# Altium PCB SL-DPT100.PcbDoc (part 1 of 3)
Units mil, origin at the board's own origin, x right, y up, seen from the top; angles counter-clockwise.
Board outline 2881.89 x 2169.29 mil, 4 copper layers (Top Layer, VCC, GND, Bottom Layer); 176 components, 168 nets, 589 pads, 369 vias.
Unrouted connection lines stored in the file: 2.
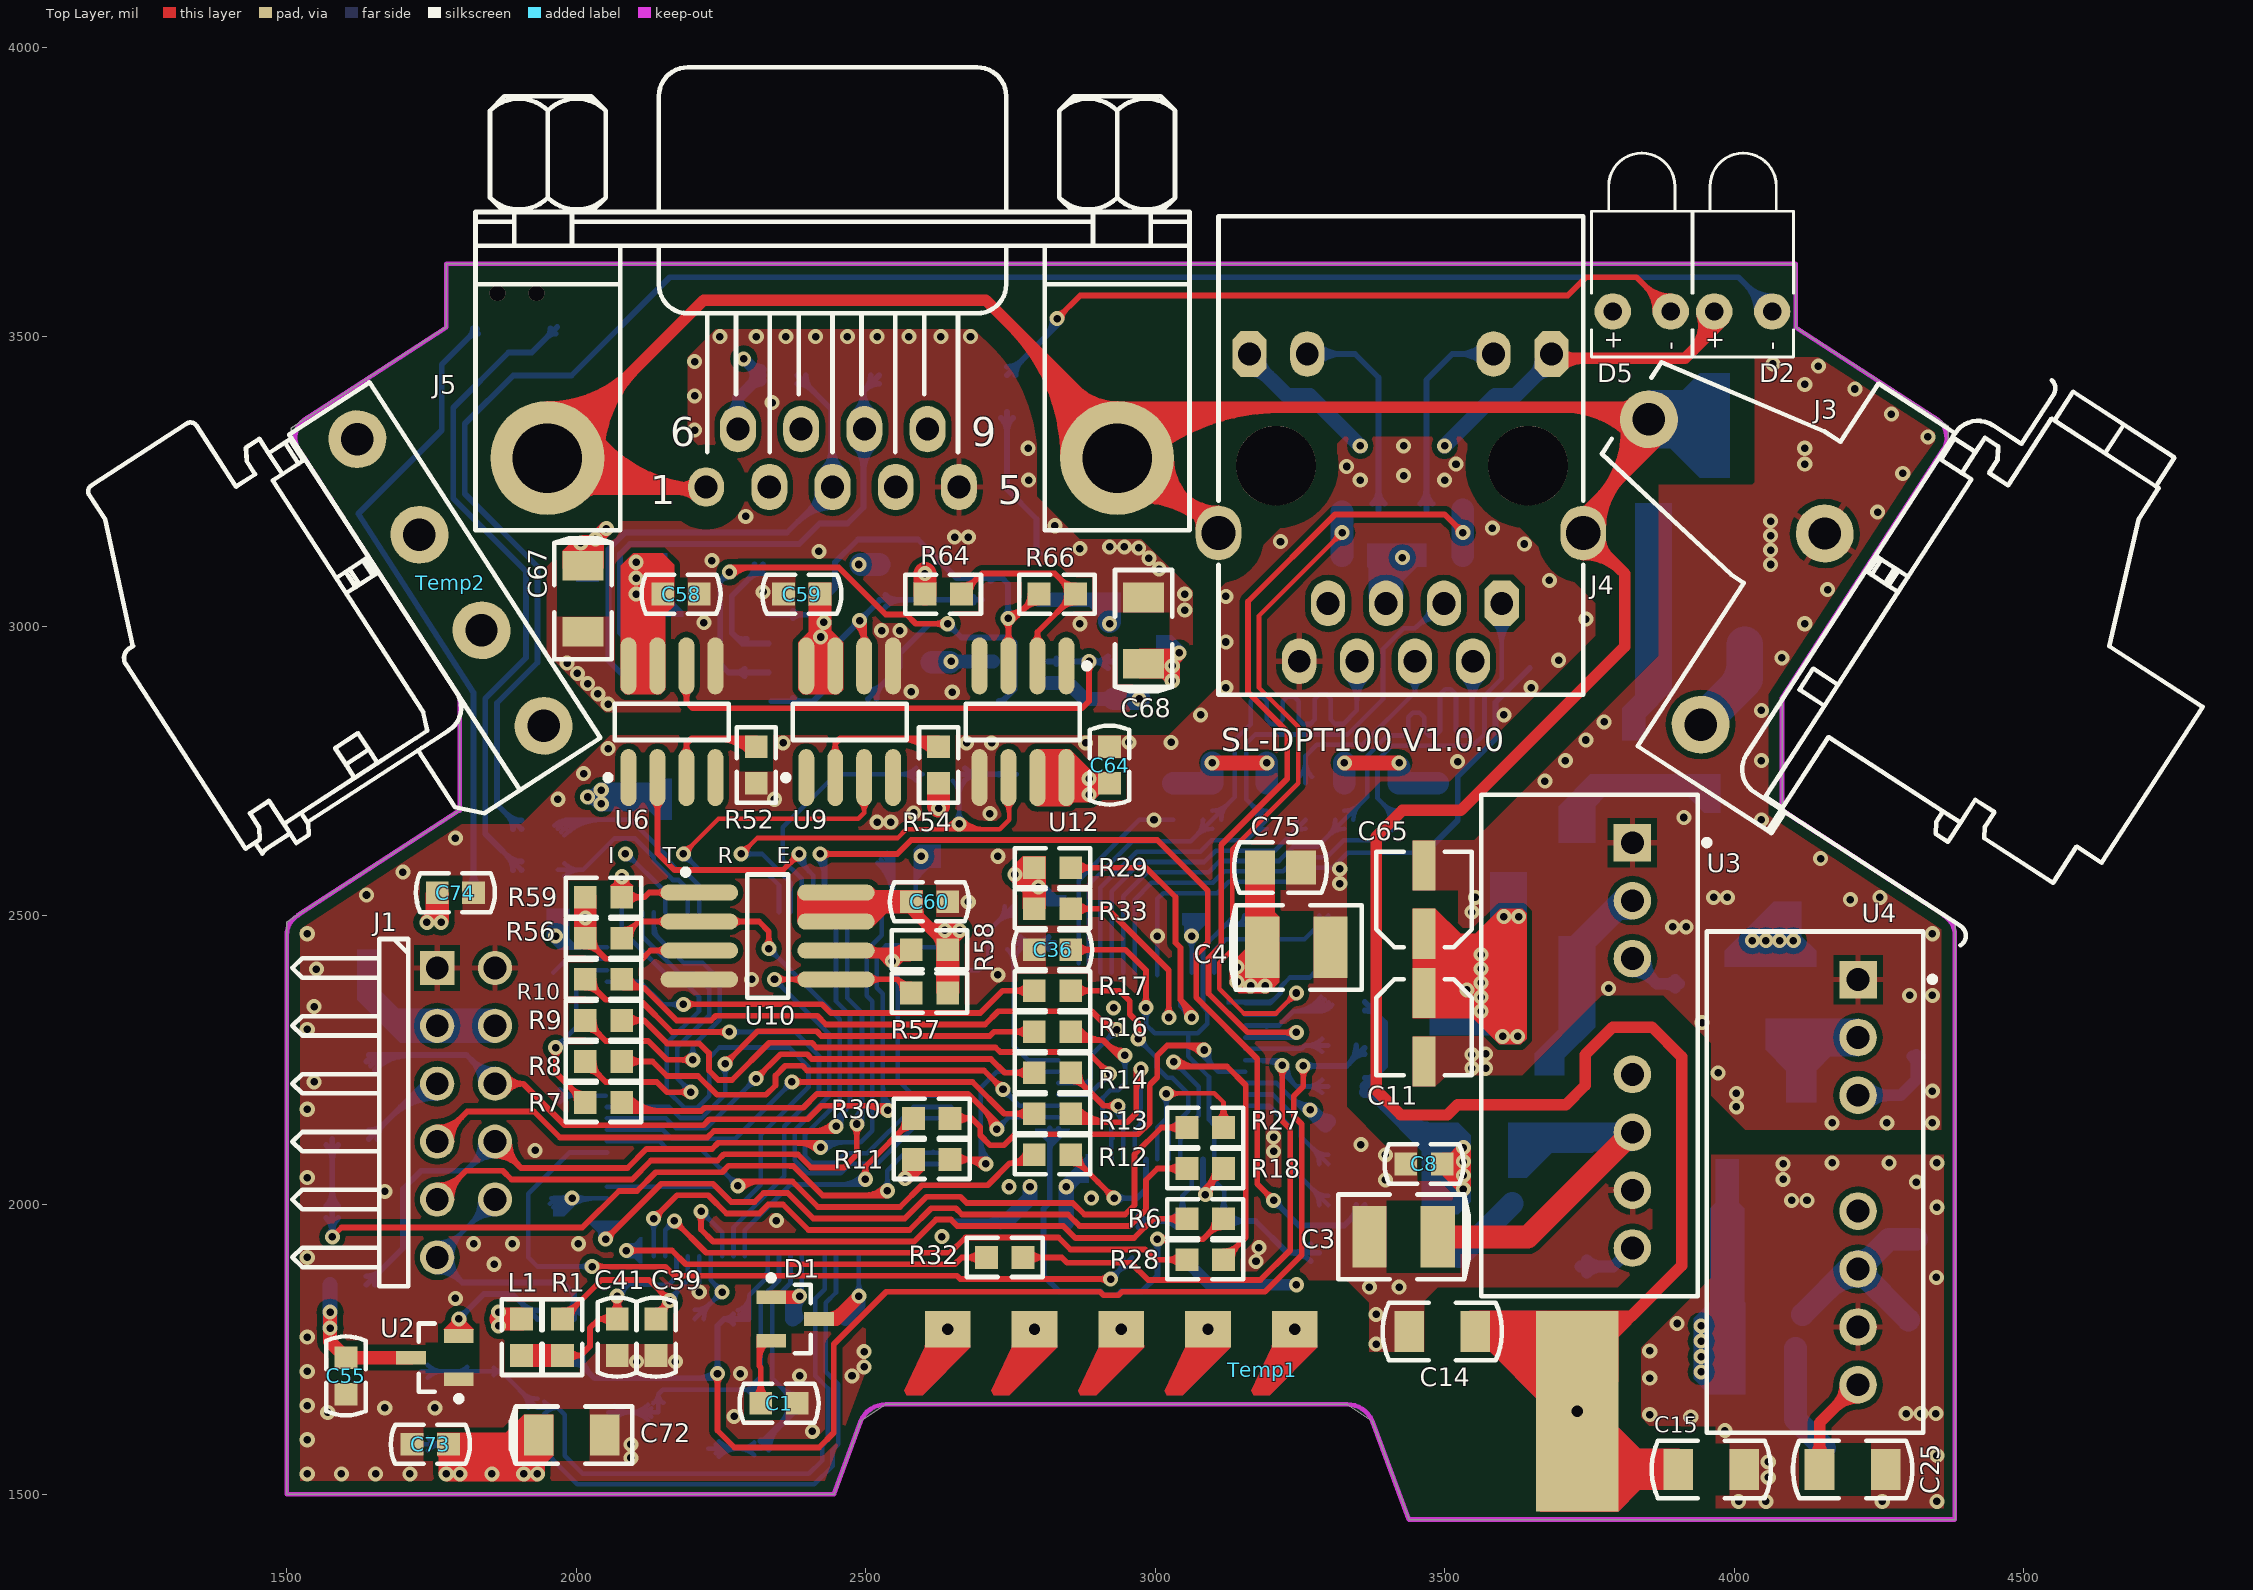
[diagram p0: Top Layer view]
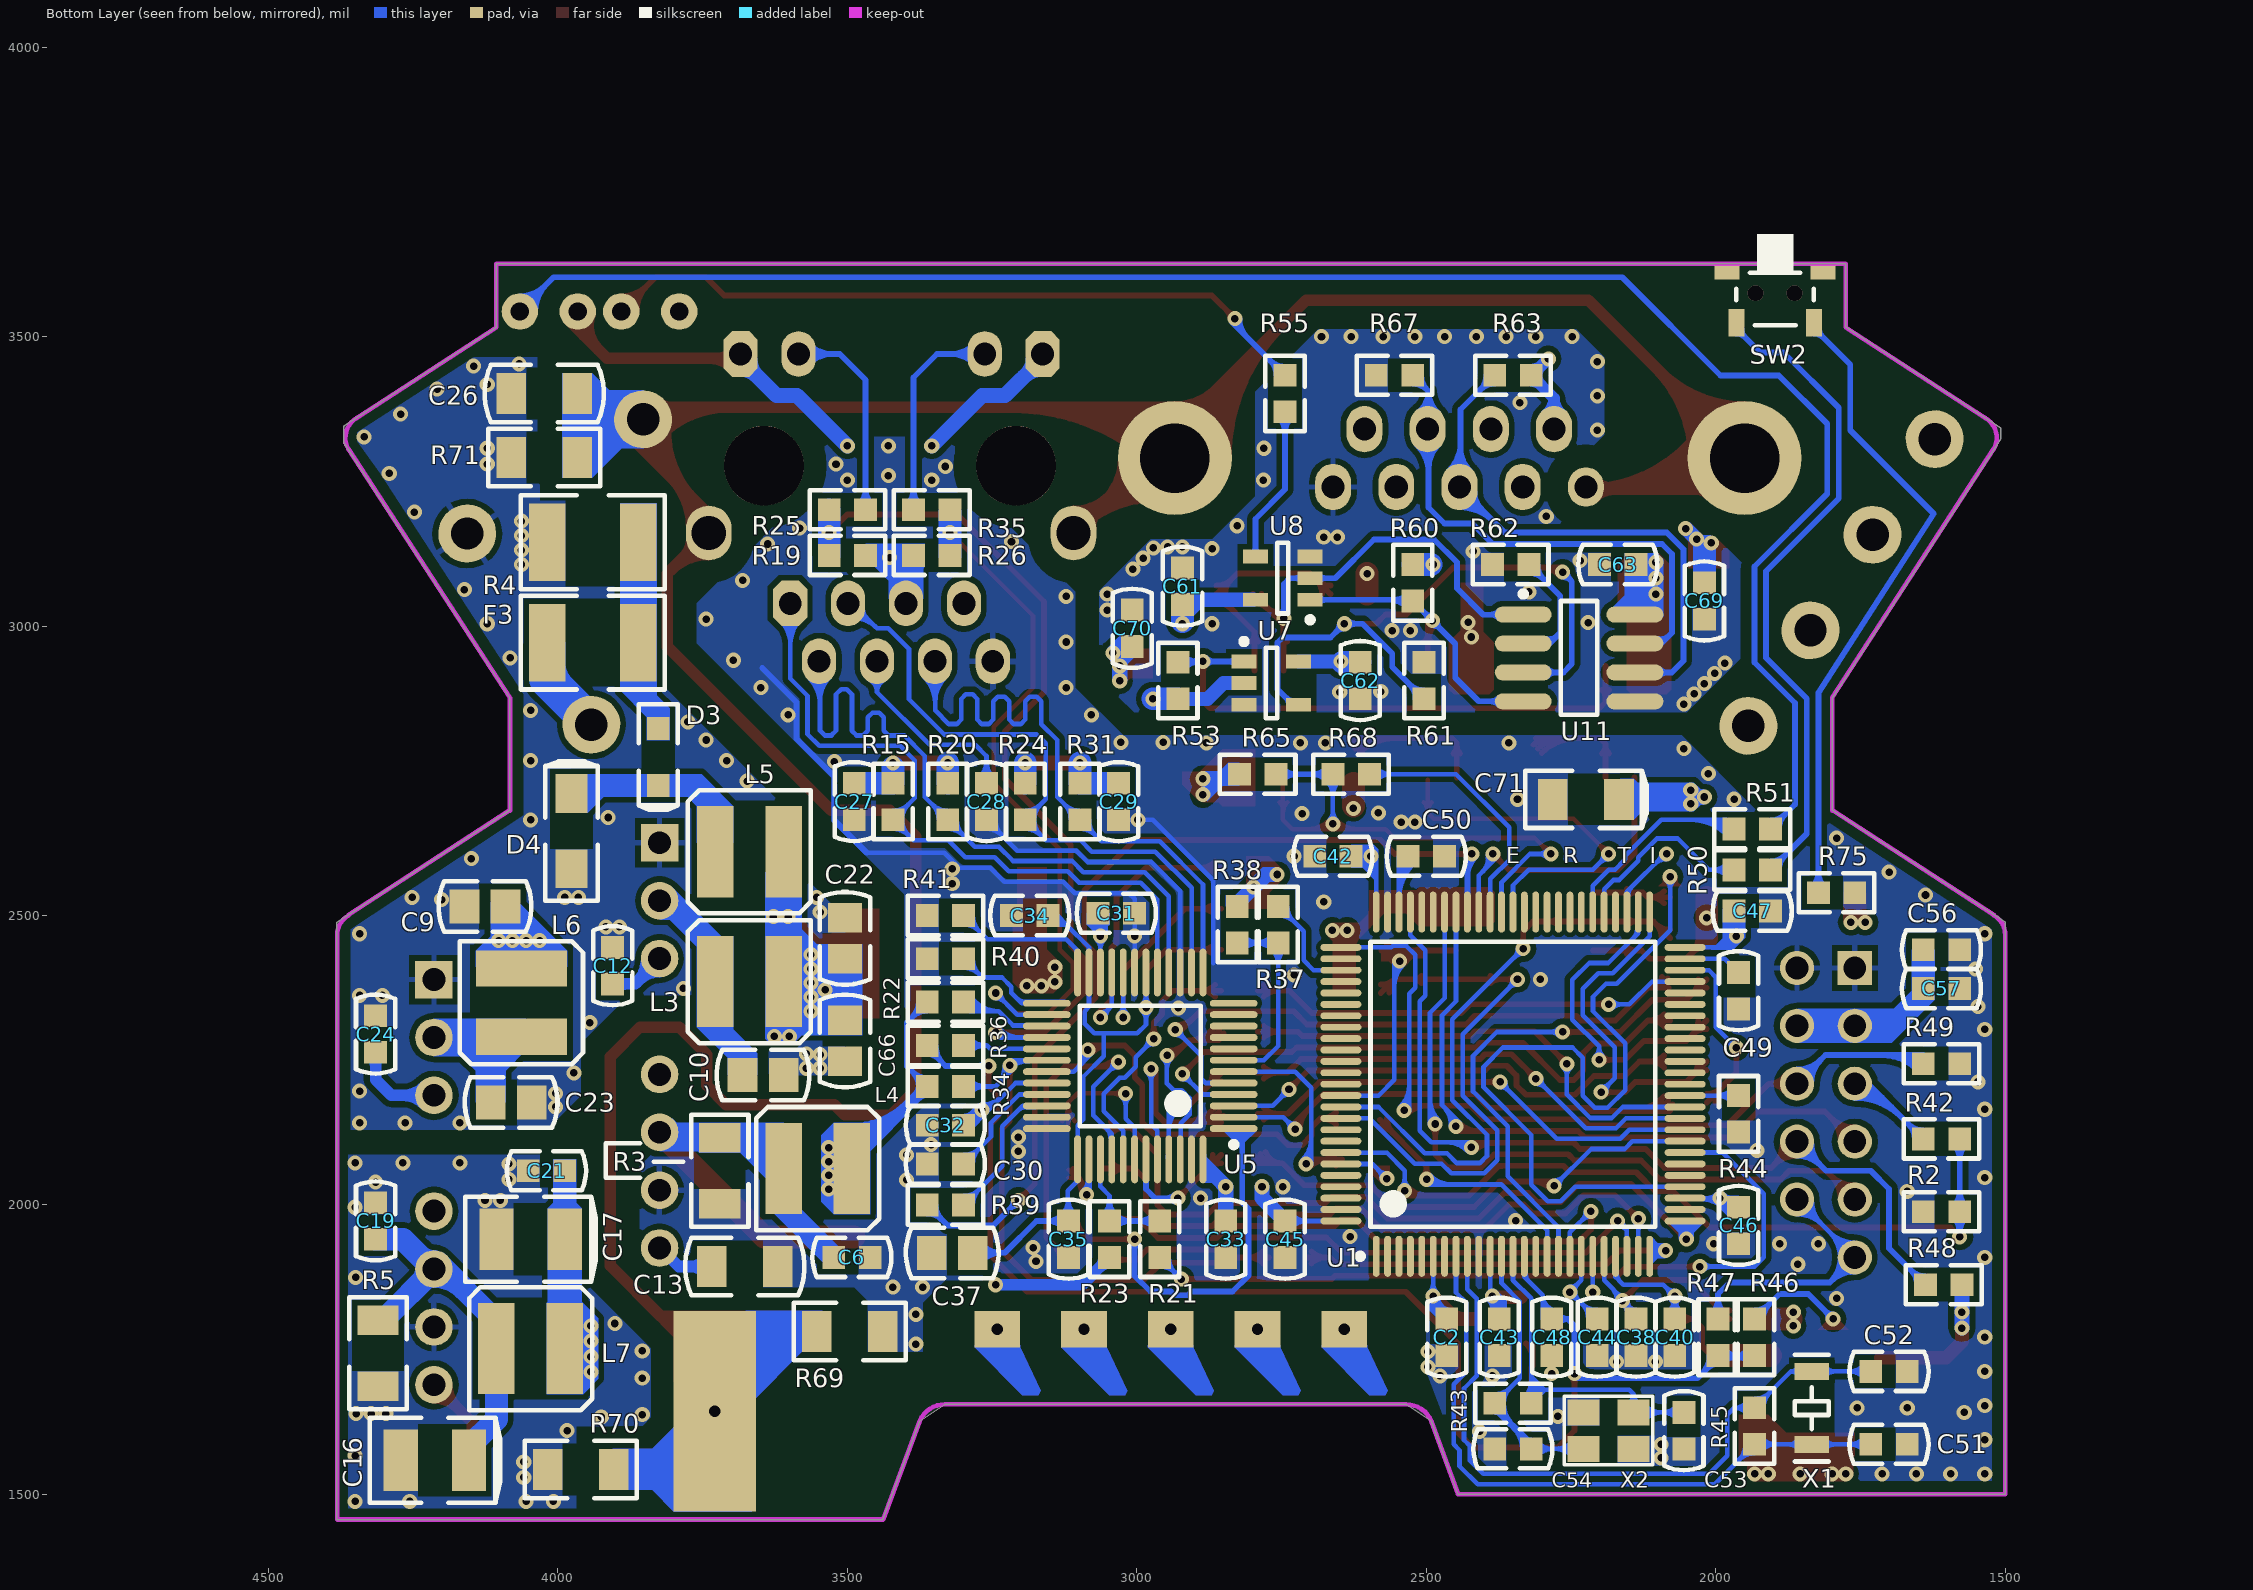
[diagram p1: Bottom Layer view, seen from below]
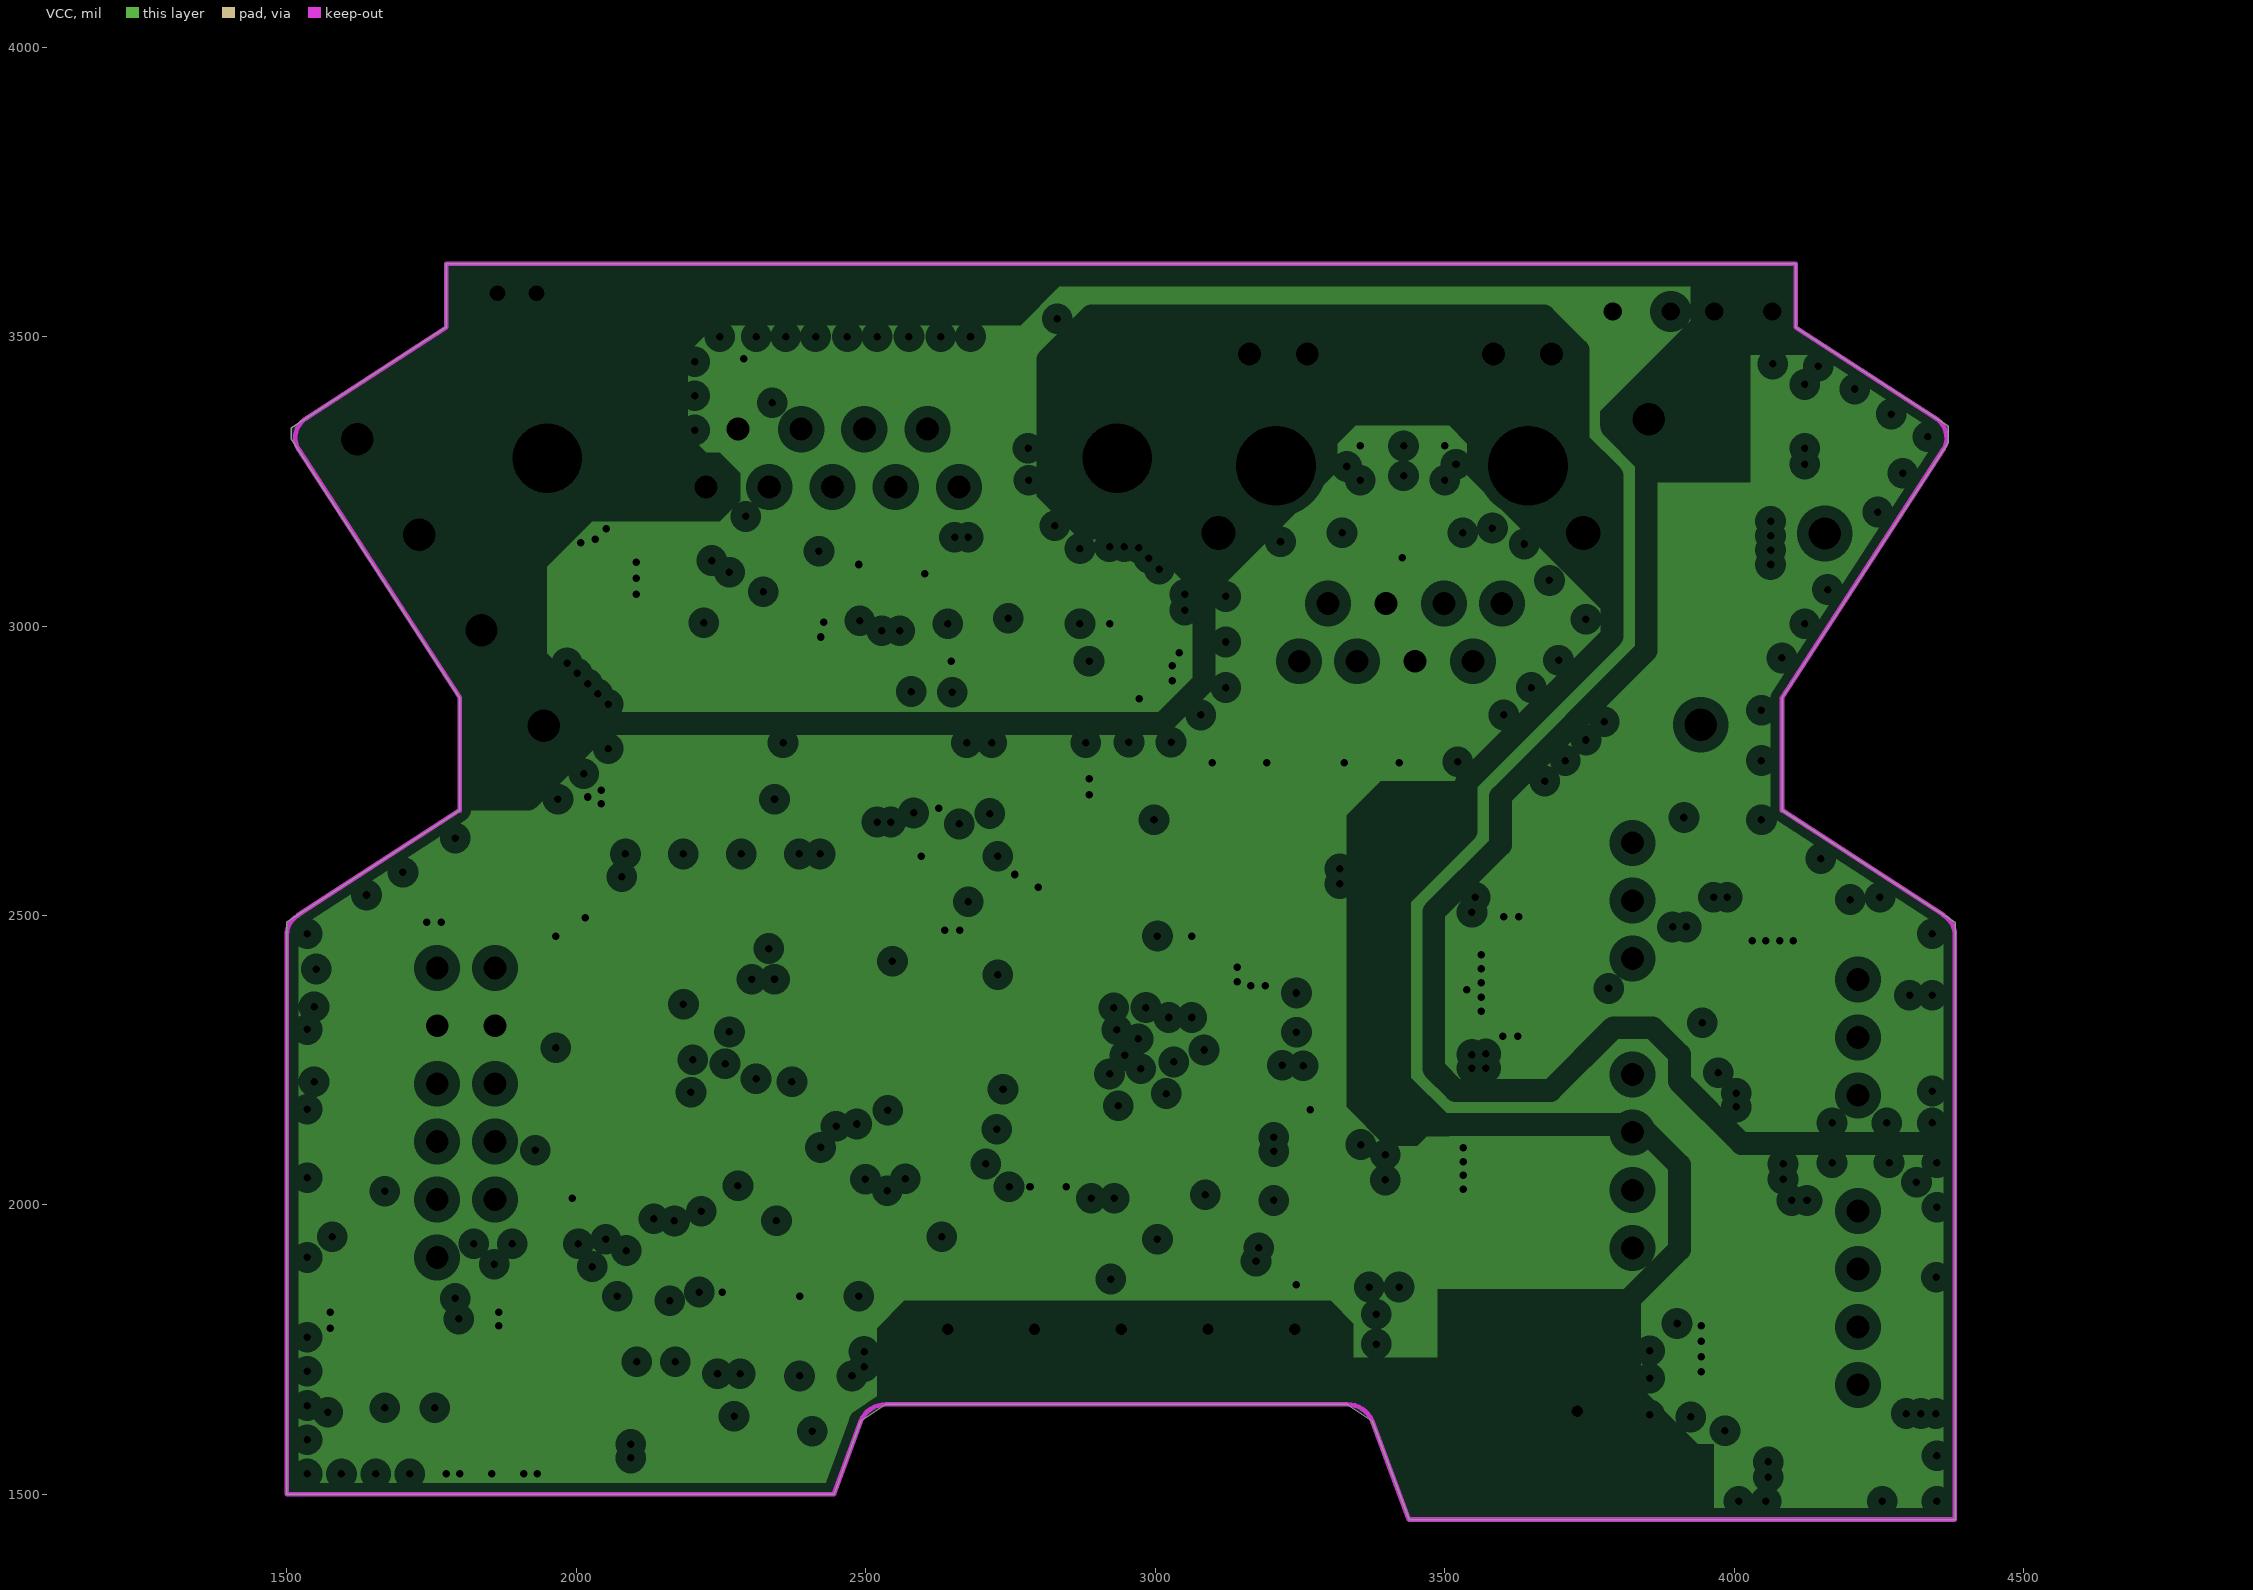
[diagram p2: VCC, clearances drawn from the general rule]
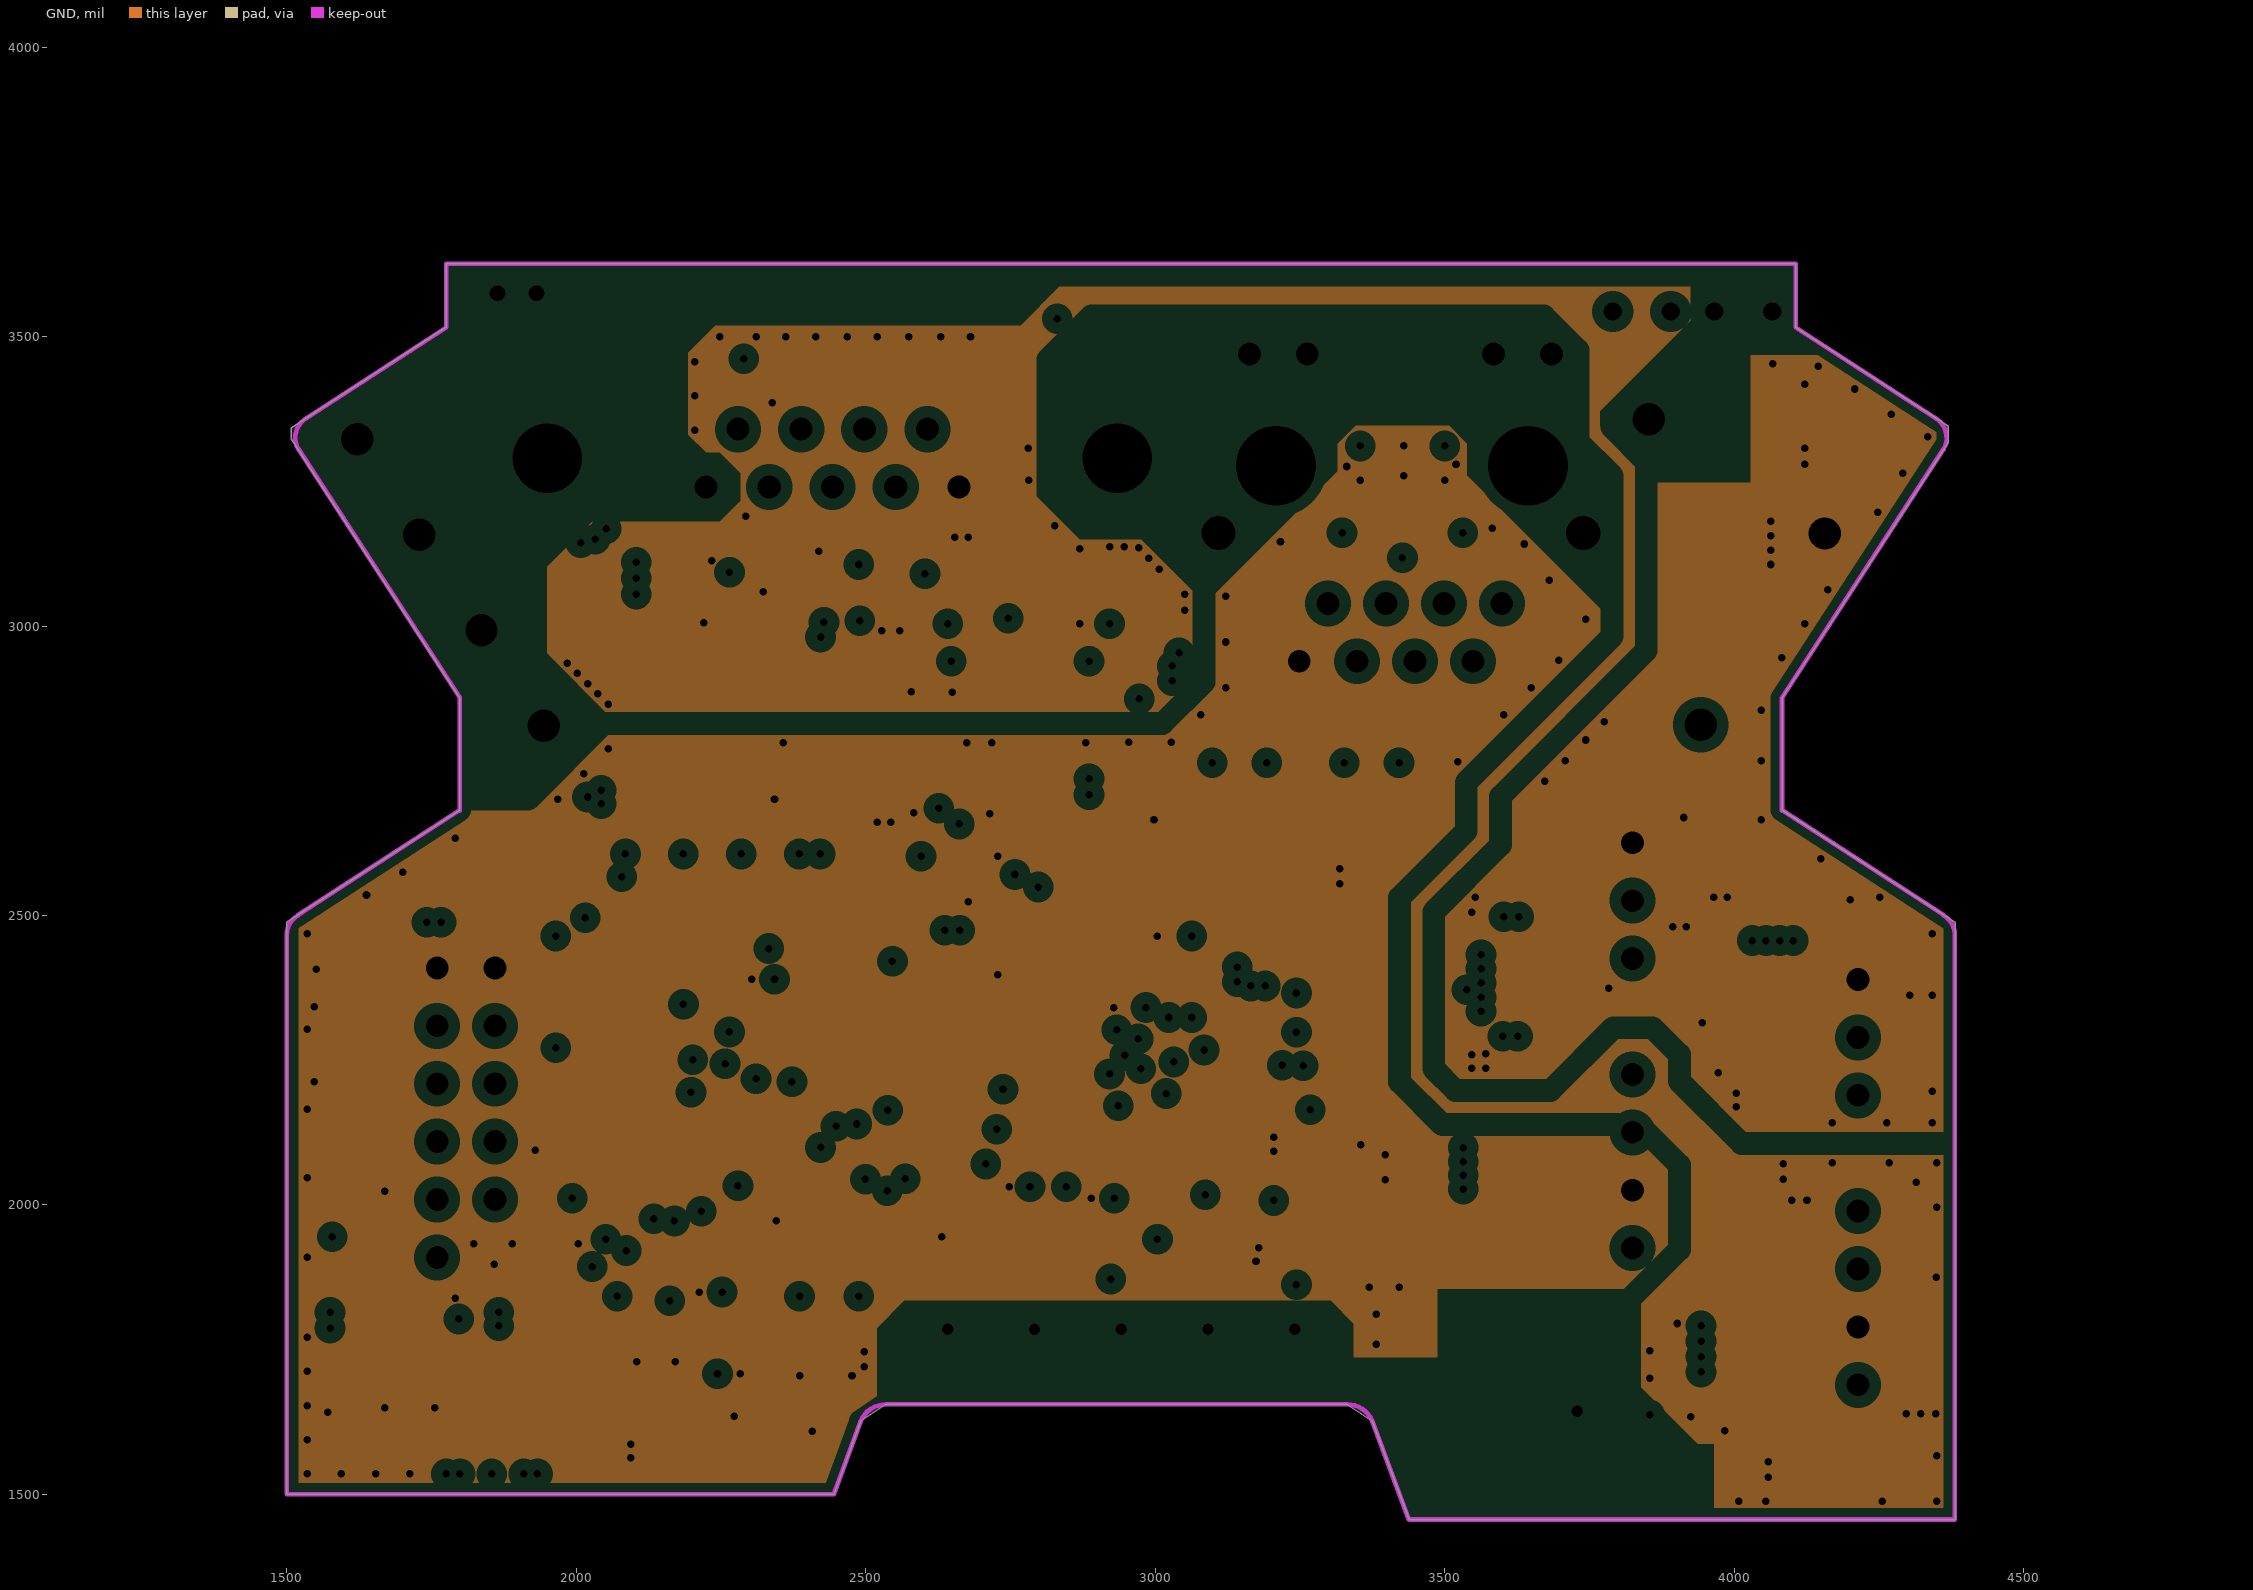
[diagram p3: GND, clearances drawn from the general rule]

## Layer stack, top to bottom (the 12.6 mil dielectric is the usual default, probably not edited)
Top Layer: signal copper 1.4
Dielectric: core 12.6, FR-4, Dk 4.8
VCC: plane copper 1.4, net (Multiple Nets)
Dielectric: prepreg 12.6, FR-4, Dk 4.8
GND: plane copper 1.4, net (Multiple Nets)
Dielectric: core 12.6, FR-4, Dk 4.8
Bottom Layer: signal copper 1.4

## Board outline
2534.62,1655.51 2491.54,1626.77 2445.28,1500 1500,1500 1500,2488.19 1798.64,2681.98 1799.1,2875.91 1507.87,3322.83 1507.87,3342.52 1775.48,3515.91 1775.59,3625.98 4106.3,3625.98 4106.41,3515.91 4370.08,3345.07 4370.08,3316.79 4082.79,2875.91 4083.25,2681.98 4381.89,2488.19 4381.84,1714.49 4381.89,1456.69 3438.98,1456.69 3374.86,1626.86 3331.79,1655.51

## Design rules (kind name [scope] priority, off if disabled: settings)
Clearance Clearance_1 [InNet('V3.3') vs InNet('NetD5_2')] p1: gap=10
Clearance Clearance_KeepOut_L [All vs OnLayer('Keep-Out Layer')] p2: gap=0.4
Clearance Clearance_V5.0 [InNetClass('NetClass V5.0') vs Not(InNetClass('NetClass V5.0') Or InComponent(D2) Or InNet(NetD2_2) Or InNet(NetD5_2))] p3: gap=39.37
Clearance Clearance_V24 [InNetClass('NetClass V24') vs Not(InNetClass('NetClass V24'))] p4: gap=39.37
Clearance Clearance_GNDE [InNetClass('NetClass GNDE') vs Not(InNetClass('NetClass GNDE'))] p5: gap=39.37
Clearance Clearance_U1_U5 [(InComponent(U1) Or InComponent(U5)) And IsComponentPad] p6: gap=7.87
Clearance [All] p7: gap=9.84
HoleSize [All] p1: absolutevalues=TRUE maxlimit=1000 minlimit=1 maxpercent=80.000 minpercent=20.000
PlaneClearance PlaneClearance_GNDE [InNetClass('NetClass GNDE')] p1: clearance=39.37
PlaneClearance [All] p2: clearance=20
PlaneConnect PlaneConnect_Via [IsVia] p1: planeconnectstyle=Direct reliefexpansion=20 reliefentries=4 reliefconductorwidth=10 reliefairgap=10
PlaneConnect [All] p2: planeconnectstyle=Relief reliefexpansion=20 reliefentries=4 reliefconductorwidth=10 reliefairgap=10
PolygonConnect PolygonConnect_1 [IsPad And OnMultiLayer] p1: connectstyle=Relief reliefconductorwidth=10 reliefentries=4 polygonreliefangle="90 Angle"
PolygonConnect [All] p2: connectstyle=Direct reliefconductorwidth=10 reliefentries=4 polygonreliefangle="90 Angle"
RoutingVias [All] p1: holewidth=13 width=26 viastyle="Through Hole" minholewidth=12 minwidth=24 maxholewidth=120 maxwidth=240
SilkToSilkClearance [All] p1: silktosilkclearance=4
SilkscreenOverComponentPads SilkscreenOverComponentPads_1 [All] p1: minsilkscreentomaskgap=0.4
SilkscreenOverComponentPads [All] p2: minsilkscreentomaskgap=10
SolderMaskExpansion [All] p1: expansion=4
Width Width_Power [InNetClass('NetClass Power')] p1 off: maxlimit=78.74 minlimit=19.68 preferedwidth=19.68
Width [All] p2: maxlimit=100 minlimit=8 preferedwidth=10
23 further rules are at their usual default settings.

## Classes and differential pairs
component class Ethernet: C27 C28 C29 C30 C31 C32 C33 C34 C35 C36 C37 J4 R6 R7 R8 R9 R10 R11 R12 R13 R14 R15 R16 R17 R18 R19 R20 R21 R22 R23 R24 R25 R26 R27 R28 R29 R30 R31 R32 R33 R34 R35 R36 R37 R38 R39 R40 R41 U5
component class MCU_1: C58 C59 C60 C61 C62 C63 C64 D2 D5 J2 J5 R50 R51 R52 R53 R54 R55 R56 R57 R58 R59 R60 R61 R62 R63 R64 R65 R66 R67 R68 R75 SW2 U1 U6 U7 U8 U9 U10 U11 U12
component class MCU: C1 C2 C38 C39 C40 C41 C42 C43 C44 C45 C46 C47 C48 C49 C50 C51 C52 C53 C54 C55 C56 C57 D1 J1 L1 R1 R2 R42 R43 R44 R45 R46 R47 R48 R49 U2 X1 X2
component class Power: C3 C4 C5 C6 C7 C8 C9 C10 C11 C12 C13 C14 C15 C16 C17 C18 C19 C20 C21 C22 C23 C24 C25 C26 C65 C66 C67 C68 C69 C70 C71 C72 C73 C74 C75 D3 D4 F3 J3 L3 L4 L5 L6 L7 R3 R4 R5 R69 R70 R71 U3 U4
net class PA[0..15]: PA0 PA1 PA2 PA3 PA4 PA5 PA6 PA7 PA8 PA9 PA10 PA11 PA12 PA13 PA14 PA15
net class PB[0..15]: PB0 PB1 PB2 PB3 PB4 PB5 PB6 PB7 PB8 PB9 PB10 PB11 PB12 PB13 PB14 PB15
net class PC[0..15]: PC0 PC1 PC2 PC3 PC4 PC5 PC6 PC7 PC8 PC9 PC10 PC11 PC12 PC13 PC14 PC15
net class PD[0..15]: PD0 PD1 PD2 PD3 PD4 PD5 PD6 PD7 PD8 PD9 PD10 PD11 PD12 PD13 PD14 PD15
net class PE[0..15]: PE0 PE1 PE2 PE3 PE4 PE5 PE6 PE7 PE8 PE9 PE10 PE11 PE12 PE13 PE14 PE15
net class "NetClass V24": NetC12_1 NetC24_1 V24+ V24+1 V24+2 V24+3 V24+4 V24+5 V24-
net class "NetClass GNDE": GNDE
net class "NetClass V5.0": 5T1 5T2 5T3 5T4 5T5 5T6 5T7 DE DE# DP-A DP-B GNDD NetC25_1 NetD5_2 NetR55_1 NetR64_1 RE# RXD TXD V5.0 V5.0_1
net class "NetClass Power": GND GNDD GNDE V3.3 V3.3_1 V5.0 V5.0_1 V24+ V24+1 V24+2 V24+3 V24+4 V24+5 V24-

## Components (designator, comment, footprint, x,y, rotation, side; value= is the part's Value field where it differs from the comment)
C1 "0.1uF" C1608(0603) 2350.39,1657.48 r180 top
C2 "0.1uF" C1608(0603) 2464.57,1771.65 r90 bottom
C3 "33uF" C3528(B) 3429.13,1944.88 r0 top
C4 "33uF" C3528(B) 3244.09,2444.88 r180 top
C6 "0.1uF" C1608(0603) 3492.13,1909.45 r180 bottom
C8 "0.1uF" C1608(0603) 3464.57,2070.87 r180 top
C9 "4.7uF/50V" C2012(0805) 4125.98,2515.75 r0 bottom
C10 "4.7uF/50V" C2012(0805) 3645.67,2224.41 r180 bottom
C11 "22uF/50V" CAPMP4X6 3464.57,2307.09 r270 top
C12 "0.1uF" C1608(0603) 3905.51,2413.39 r270 bottom
C13 "10uF/50V" C3216(1206) 3677.17,1893.7 r180 bottom
C14 "1000pF/2KV" C3216(1206) 3496.06,1781.5 r0 top
C15 "1000pF/2KV" C3216(1206) 3960.63,1543.31 r180 top
C16 "33uF" C3528(B) 4212.6,1559.06 r180 bottom
C17 "33uF" C3528(B) 4047.24,1940.94 r180 bottom
C19 "0.1uF" C1608(0603) 4314.96,1972.44 r90 bottom
C21 "0.1uF" C1608(0603) 4019.68,2059.06 r0 bottom
C22 "4.7uF/50V" C2012(0805) 3503.94,2460.63 r90 bottom
C23 "4.7uF/50V" C2012(0805) 4080.71,2177.17 r180 bottom
C24 "0.1uF" C1608(0603) 4314.96,2295.28 r270 bottom
C25 "10uF/50V" C3216(1206) 4204.72,1543.31 r0 top
C26 "1000pF/2KV" C3216(1206) 4023.62,3401.57 r180 bottom
C27 "0.1uF" C1608(0603) 3488.19,2696.85 r90 bottom
C28 "0.1uF" C1608(0603) 3259.84,2696.85 r90 bottom
C29 "0.1uF" C1608(0603) 3031.5,2696.85 r90 bottom
C30 "22pF" C1608(0603) 3330.71,2070.87 r0 bottom
C31 "0.1uF" C1608(0603) 3035.43,2503.94 r180 bottom
C32 "0.1uF" C1608(0603) 3330.71,2137.8 r0 bottom
C33 "0.1uF" C1608(0603) 2846.46,1940.94 r270 bottom
C34 "0.1uF" C1608(0603) 3185.04,2500 r0 bottom
C35 "0.1uF" C1608(0603) 3118.11,1940.94 r270 bottom
C36 "0.1uF" C1608(0603) 2822.83,2440.94 r180 top
C37 "10uF" C2012(0805) 3318.9,1917.32 r180 bottom
C38 "0.1uF" C1608(0603) 2137.8,1771.65 r90 bottom
C39 "2.2uF" C1608(0603) 2137.8,1771.65 r90 top
C40 "0.1uF" C1608(0603) 2070.87,1771.65 r90 bottom
C41 "2.2uF" C1608(0603) 2070.87,1771.65 r90 top
C42 "0.1uF" C1608(0603) 2661.42,2602.36 r180 bottom
C43 "0.1uF" C1608(0603) 2374.02,1771.65 r90 bottom
C44 "0.1uF" C1608(0603) 2204.72,1771.65 r90 bottom
C45 "0.1uF" C1608(0603) 2744.09,1940.94 r90 bottom
C46 "0.1uF" C1608(0603) 1960.63,1964.65 r90 bottom
C47 "0.1uF" C1608(0603) 1937.01,2507.87 r0 bottom
C48 "0.1uF" C1608(0603) 2283.46,1771.65 r90 bottom
C49 "2.2uF" C1608(0603) 1960.63,2370.08 r90 bottom
C50 "2.2uF" C1608(0603) 2500.08,2602.36 r0 bottom
C51 "22pF" C1608(0603) 1700.79,1586.61 r180 bottom
C52 "22pF" C1608(0603) 1700.79,1712.6 r180 bottom
C53 "22pF" C1608(0603) 2055.12,1610.24 r270 bottom
C54 "22pF" C1608(0603) 2350.39,1578.74 r0 bottom
C55 "0.1uF" C1608(0603) 1602.36,1704.72 r90 top
C56 "2.2uF" C1608(0603) 1610.24,2440.94 r0 bottom
C57 "0.1uF" C1608(0603) 1610.24,2374.02 r180 bottom
C58 "0.1uF" C1608(0603) 2181.1,3055.12 r180 top
C59 "0.1uF" C1608(0603) 2389.76,3055.12 r0 top
C60 "0.1uF" C1608(0603) 2610.24,2523.62 r180 top
C61 "0.1uF" C1608(0603) 2921.26,3068.9 r90 bottom
C62 "0.1uF" C1608(0603) 2614.17,2905.91 r90 bottom
C63 "0.1uF" C1608(0603) 2169.29,3106.3 r180 bottom
C64 "0.1uF" C1608(0603) 2921.26,2759.84 r270 top
C65 "22uF/50V" CAPMP4X6 3464.57,2527.56 r90 top
C66 "4.7uF/50V" C2012(0805) 3503.94,2283.46 r270 bottom
C67 "10uF" C3216(A) 2011.81,3047.24 r270 top
C68 "10uF" C3216(A) 2980.32,2992.13 r90 top
C69 "0.1uF" C1608(0603) 2019.68,3043.31 r270 bottom
C70 "0.1uF" C1608(0603) 3007.87,2996.06 r90 bottom
C71 "10uF" C3216(A) 2224.41,2700.79 r0 bottom
C72 "10uF" C3216(A) 1992.13,1602.36 r0 top
C73 "0.1uF" C1608(0603) 1748.03,1586.61 r180 top
C74 "0.1uF" C1608(0603) 1791.34,2539.37 r0 top
C75 "10uF" C2012(0805) 3216.54,2582.68 r0 top
D1 "BAT54C" SOT23-3_N 2377.95,1803.15 r180 top
D2 "LED0" LED-1 4015.75,3543.31 r90 top locked
D3 "1A/30V" SOD323 3826.77,2773.62 r270 bottom
D4 "SMF24A" SOD123 3976.38,2645.67 r90 bottom
D5 "LED0" LED-1 3840.55,3543.31 r90 top locked
F3 "SMD1812P050TF/30" R4532(1812) 3939.92,2971.54 r0 bottom
J1 "H2.54 6X2" HDR2X6H 1759.84,2409.45 r270 top locked
J3 "Header 3" "MKDSO2.5 HV/3R-7.5" 4156.69,3159.84 r327 top locked
J4 "HR911105A" RJ45-LED 3598.43,3039.37 r0 top locked
J5 "D Connector 9" DB9F 2224.41,3240.16 r0 top locked
L1 "FCM1608KF-601T03" R1608(0603) 1905.51,1771.65 r270 top
L3 "10uH/1A" L4040 3669.29,2385.83 r0 bottom
L4 "10uH/1A" L4040 3551.18,2062.99 r180 bottom
L5 "68uH/0.5A" L4040 3669.29,2610.24 r0 bottom
L6 "10uH/1A" L4040 4062.99,2349.41 r270 bottom
L7 "10uH/1A" L4040 4047.24,1751.97 r180 bottom
R1 "0R" R1608(0603) 1976.38,1771.65 r270 top
R2 "2.2K" R1608(0603) 1610.24,1988.19 r180 bottom
R3 "82R" R3216(1206) 3720.47,2059.06 r90 bottom
R4 "MLV1812NA030" R4532(1812) 3939.92,3144.76 r180 bottom
R5 "82R" R3216(1206) 4311.02,1744.09 r90 bottom
R6 "33R" R1608(0603) 3086.61,1976.38 r0 top
R7 "33R" R1608(0603) 2047.24,2177.17 r0 top
R8 "33R" R1608(0603) 2047.24,2248.03 r0 top
R9 "33R" R1608(0603) 2047.24,2318.9 r0 top
R10 "33R" R1608(0603) 2047.24,2389.76 r0 top
R11 "33R" R1608(0603) 2614.17,2078.74 r0 top
R12 "33R" R1608(0603) 2822.83,2086.61 r0 top
R13 "33R" R1608(0603) 2822.83,2157.48 r0 top
R14 "33R" R1608(0603) 2822.83,2228.35 r0 top
R15 "49.9R" R1608(0603) 3421.26,2696.85 r270 bottom
R16 "33R" R1608(0603) 2822.83,2299.21 r0 top
R17 "33R" R1608(0603) 2822.83,2370.08 r0 top
R18 "33R" R1608(0603) 3086.61,2062.99 r0 top
R19 "2.2K" R1608(0603) 3500,3122.05 r180 bottom
R20 "49.9R" R1608(0603) 3326.77,2696.85 r270 bottom
R21 "33R" R1608(0603) 2960.63,1940.94 r90 bottom
R22 "2.2K" R1608(0603) 3330.71,2350.39 r0 bottom
R23 "2.2K" R1608(0603) 3047.24,1940.94 r90 bottom
R24 "49.9R" R1608(0603) 3192.91,2696.85 r270 bottom
R25 "680R" R1608(0603) 3500,3200.79 r180 bottom
R26 "2.2K" R1608(0603) 3354.33,3122.05 r0 bottom
R27 "33R" R1608(0603) 3086.61,2133.86 r0 top
R28 "33R" R1608(0603) 3086.61,1905.51 r0 top
R29 "2.2K" R1608(0603) 2822.83,2582.68 r180 top
R30 "33R" R1608(0603) 2614.17,2149.61 r0 top
R31 "49.9R" R1608(0603) 3098.43,2696.85 r270 bottom
R32 "33R" R1608(0603) 2740.16,1909.45 r0 top
R33 "2.2K" R1608(0603) 2822.83,2511.81 r180 top
R34 "2.2K" R1608(0603) 3330.71,2204.72 r180 bottom
R35 "680R" R1608(0603) 3354.33,3200.79 r0 bottom
R36 "33R" R1608(0603) 3330.71,2275.59 r180 bottom
R37 "33R" R1608(0603) 2755.91,2484.25 r270 bottom
R38 "2.2K" R1608(0603) 2826.77,2484.25 r270 bottom
R39 "33R" R1608(0603) 3330.71,2000 r180 bottom
R40 "2.2K" R1608(0603) 3330.71,2425.2 r180 bottom
R41 "4.78K" R1608(0603) 3330.71,2500 r180 bottom
R42 "330R" R1608(0603) 1610.24,2114.17 r0 bottom
R43 "1M" R1608(0603) 2350.39,1657.48 r0 bottom
R44 "680R" R1608(0603) 1960.63,2157.48 r270 bottom
R45 "1M" R1608(0603) 1933.07,1618.11 r90 bottom
R46 "680R" R1608(0603) 1933.07,1771.65 r270 bottom
R47 "33R" R1608(0603) 1996.06,1771.65 r90 bottom
R48 "100K" R1608(0603) 1606.3,1862.2 r180 bottom
R49 "100K" R1608(0603) 1610.24,2244.09 r180 bottom
R50 "330R" R1608(0603) 1937.01,2578.74 r0 bottom
R51 "330R" R1608(0603) 1937.01,2649.61 r0 bottom
R52 "680R" R1608(0603) 2311.02,2759.84 r270 top
R53 "680R" R1608(0603) 2929.13,2905.91 r90 bottom
R54 "680R" R1608(0603) 2625.98,2759.84 r270 top
R55 "330R" R1608(0603) 2744.09,3401.57 r270 bottom
R56 "100K" R1608(0603) 2047.24,2460.63 r0 top
R57 "100K" R1608(0603) 2610.24,2366.14 r180 top
R58 "100K" R1608(0603) 2610.24,2440.94 r180 top
R59 "100K" R1608(0603) 2047.24,2531.5 r0 top
R60 "680R" R1608(0603) 2503.94,2905.91 r90 bottom
R61 "680R" R1608(0603) 2523.62,3074.8 r270 bottom
R62 "680R" R1608(0603) 2354.33,3106.3 r180 bottom
R63 "100K" R1608(0603) 2350.39,3433.07 r0 bottom
R64 "330R" R1608(0603) 2633.86,3055.12 r0 top
R65 "680R" R1608(0603) 2791.34,2744.09 r180 bottom
R66 "680R" R1608(0603) 2830.71,3055.12 r180 top
R67 "100K" R1608(0603) 2555.12,3433.07 r0 bottom
R68 "0R" R1608(0603) 2629.92,2744.09 r180 bottom
R69 "1M" R3216(1206) 3496.06,1781.5 r180 bottom
R70 "1M" R3216(1206) 3960.63,1543.31 r0 bottom
R71 "1M" R3216(1206) 4023.62,3291.34 r0 bottom
R75 "330R" R1608(0603) 1791.34,2539.37 r0 bottom
SW2 "SW-PB" KEY2X4 1897.64,3574.8 r180 bottom locked
Temp1 "Comment" "ME22.5 TBUS1.5/5" 2941.71,1655.51 r0 top locked
Temp2 "Comment" "MKDSO 2.5/4-L" 1782.87,3075.2 r33 top locked
U1 "STM32F407VGT6" TQFP100_N 2350.39,2208.66 r90 bottom locked
U2 "MAX809TEUR" SOT23-3_N 1755.91,1736.22 r0 top
U3 "WRB2403S-3WR2" SIP8 3724.41,2275.59 r270 top locked
U4 "WRB2405S-3WR2" SIP8 4114.17,2039.37 r270 top locked
U5 "DP83848IVV" LQFP48_M 2994.09,2240.16 r0 bottom locked
U6 "HCPL-060L" SO8_M 2165.35,2834.65 r90 top
U7 "SN74LVC1G132" SOT23-5_N 2767.72,2901.48 r180 bottom
U8 "SN74LVC1G132" SOT23-5_N 2748.03,3082.68 r0 bottom
U9 "HCPL-060L" SO8_M 2472.44,2834.65 r90 top
U10 "W25Q16DVSSI" SOIC8_M 2330.71,2464.57 r0 top locked
U11 "VP1176" SO8_M 2236.22,2944.88 r180 bottom
U12 "HCPL-060L" SO8_M 2771.65,2834.65 r270 top
X1 "32.768K" FC-135 1834.65,1649.61 r270 bottom
X2 "25MHz" XTAL-3225 2185.04,1610.24 r180 bottom

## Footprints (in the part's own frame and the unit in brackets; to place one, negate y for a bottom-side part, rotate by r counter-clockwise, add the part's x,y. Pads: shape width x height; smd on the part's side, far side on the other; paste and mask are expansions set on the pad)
C1608(0603) [mm] "Chip Capacitor, Body 1.6x0.8mm, IPC Medium Density"
  rect 1x1 smd: 1(0.8,0) 2(-0.8,0)
  Top Layer pour cut-out: -0.3,0.75 0.3,0.75 0.3,-0.75 -0.3,-0.75
  silkscreen extent -1.73,-0.86 1.73,0.86, body extent -0.87,-0.48 0.87,0.48, height 0.85
C2012(0805) [mm] "Chip Capacitor, Body 2.0x1.3mm, IPC Medium Density"
  rect 1.3x1.5 smd: 1(0.9,0) 2(-0.9,0)
  Top Layer pour cut-out: -0.25,-1 0.25,-1 0.25,1 -0.25,1
  silkscreen extent -2.03,-1.11 2.03,1.11, body extent -1.1,-0.72 1.1,0.72, height 1.1
C3216(1206) [mm] "Chip Capacitor, Body 3.2x1.6mm, IPC Medium Density"
  rect 1.3x1.8 smd: 1(-1.45,0) 2(1.45,0)
  Top Layer pour cut-out: -0.8,1.15 0.8,1.15 0.8,-1.15 -0.8,-1.15
  silkscreen extent -2.61,-1.26 2.61,1.26, body extent -1.7,-0.9 1.7,0.9, height 1.35
C3216(A) [mm] "Chip Capacitor, Body 3.2x1.6mm, IPC Medium Density"
  rect 1.3x1.8 smd: 1(-1.45,0) 2(1.45,0)
  Top Layer pour cut-out: -0.8,1.15 0.8,1.15 0.8,-1.15 -0.8,-1.15
  silkscreen extent -2.66,-1.26 2.66,1.26, body extent -1.7,-0.9 1.7,0.9, height 1.35
C3528(B) [mm] "Chip Capacitor, Body 3.5x2.8mm, IPC Medium Density"
  rect 1.5x2.7 smd: 1(1.5,0) 2(-1.5,0)
  Top Layer pour cut-out: 0.75,-1.6 -0.75,-1.6 -0.75,1.6 0.75,1.6
  silkscreen extent -2.86,-1.86 2.86,1.86, body extent -1.7,-1.35 1.7,1.35, height 1.35
CAPMP4X6 [mm] "Molded Capacitor, 2-Leads, Body 4.3mmx6.1mm, IPC High Density"
  rect 2.2x1 smd: 1(-1.5,0) 2(1.5,0)
  silkscreen extent -2.1,-2.1 2.1,2.1
DB9F [mil]
  oval 62x68 hole 40: 1(0,0)
  oval 62x80 hole 40: 2(109.17,0) 3(218.33,0) 4(327.5,0) 5(436.67,0) 6(55,100) 7(164.17,100) 8(273.33,100) 9(382.5,100)
  round 196.67 hole 120: 10(-274.17,50) 11(710,50)
  silkscreen extent -398,-75 835,725
FC-135 [mm]
  rect 0.75x1.5 smd: 1(-1.6,0.011) 2(1.6,0.011)
  Top Layer pour cut-out: -1.22,1.01 -1.22,-0.99 1.23,-0.99 1.23,1.01
  silkscreen extent -2.33,-0.74 2.35,0.76
HDR2X6H [mm] "Connector; Header; 6x2 Position; Right Angle"
  rect 1.5x1.5 hole 1: 1(0,0)
  round 1.5 hole 1: 2(0,2.54) 3(2.54,0) 4(2.54,2.54) 5(5.08,0) 6(5.08,2.54) 7(7.62,0) 8(7.62,2.54) 9(10.16,0) 10(10.16,2.54) 11(12.7,0)
  silkscreen extent -1.27,-6.35 13.97,-1.27
KEY2X4 [mm]
  rect 0.7x1.2 smd: 1(-1.7,-1.3) 2(1.7,-1.3)
  rect 1.1x0.7 smd: 3(2.1,0.95) 4(-2.1,0.95)
  silkscreen extent -1.7,-1.4 1.7,2.6
L4040 [mm] "Chip Inductor, Body 4.0x4.0mm, IPC Medium Density"
  rect 1.6x4 smd: 1(-1.5,0) 2(1.5,0)
  Top Layer pour cut-out: -0.7,2.25 0.7,2.25 0.7,-2.25 -0.7,-2.25
  silkscreen extent -2.7,-2.7 2.7,2.7, body extent -2,-2 2,2, height 0.71
LED-1 [mm] "Typical RED GaAs LED; 2 Leads"
  round 1.6 hole 0.8: 1(0,1.27) 2(0,-1.27)
  silkscreen extent -2,-2.2 6.95,2.2
LQFP48_M [mm] "48-Pin Thin Quad Flat Pack 0.5 mm Pitch, IPC Low Density"
  oval 2.1x0.3 smd: 1(-4.1,2.75) 2(-4.1,2.25) 3(-4.1,1.75) 4(-4.1,1.25) 5(-4.1,0.75) 6(-4.1,0.25) 7(-4.1,-0.25) 8(-4.1,-0.75) 9(-4.1,-1.25) 10(-4.1,-1.75) 11(-4.1,-2.25) 12(-4.1,-2.75) 25(4.1,-2.75) 26(4.1,-2.25) 27(4.1,-1.75) 28(4.1,-1.25) 29(4.1,-0.75) 30(4.1,-0.25) 31(4.1,0.25) 32(4.1,0.75) 33(4.1,1.25) 34(4.1,1.75) 35(4.1,2.25) 36(4.1,2.75)
  oval 0.3x2.1 smd: 13(-2.75,-4.1) 14(-2.25,-4.1) 15(-1.75,-4.1) 16(-1.25,-4.1) 17(-0.75,-4.1) 18(-0.25,-4.1) 19(0.25,-4.1) 20(0.75,-4.1) 21(1.25,-4.1) 22(1.75,-4.1) 23(2.25,-4.1) 24(2.75,-4.1) 37(2.75,4.1) 38(2.25,4.1) 39(1.75,4.1) 40(1.25,4.1) 41(0.75,4.1) 42(0.25,4.1) 43(-0.25,4.1) 44(-0.75,4.1) 45(-1.25,4.1) 46(-1.75,4.1) 47(-2.25,4.1) 48(-2.75,4.1)
  silkscreen extent -4.22,-2.65 2.65,3.57, body extent -3.5,-3.5 3.5,3.5, height 1.6
"ME22.5 TBUS1.5/5" [mm]
  rect 2x1.6 hole 0.5: 1(-7.62,3.3) 2(-3.81,3.3) 3(0,3.3) 4(3.8,3.3) 5(7.6,3.3)
  rect 3.6x8.8 hole 0.5: 6(20,-0.3)
  Top Layer region: -6.62,2.6 -6.62,2.5 -8.72,0.4 -9.42,0.4 -9.52,0.6 -8.62,2.5 -8.62,2.6
  Top Layer region: -2.81,2.6 -2.81,2.5 -4.91,0.4 -5.61,0.4 -5.71,0.6 -4.81,2.5 -4.81,2.6
  Top Layer region: 8.6,2.6 8.6,2.5 6.5,0.4 5.8,0.4 5.7,0.6 6.6,2.5 6.6,2.6
  Top Layer region: 4.8,2.6 4.8,2.5 2.7,0.4 2,0.4 1.9,0.6 2.8,2.5 2.8,2.6
  Top Layer region: 1,2.6 1,2.5 -1.1,0.4 -1.8,0.4 -1.9,0.6 -1,2.5 -1,2.6
  Bottom Layer region: -6.62,2.6 -6.62,2.5 -8.72,0.4 -9.42,0.4 -9.52,0.6 -8.62,2.5 -8.62,2.6
  Bottom Layer region: -2.81,2.6 -2.81,2.5 -4.91,0.4 -5.61,0.4 -5.71,0.6 -4.81,2.5 -4.81,2.6
  Bottom Layer region: 8.6,2.6 8.6,2.5 6.5,0.4 5.8,0.4 5.7,0.6 6.6,2.5 6.6,2.6
  Bottom Layer region: 4.8,2.6 4.8,2.5 2.7,0.4 2,0.4 1.9,0.6 2.8,2.5 2.8,2.6
  Bottom Layer region: 1,2.6 1,2.5 -1.1,0.4 -1.8,0.4 -1.9,0.6 -1,2.5 -1,2.6
  Keep-Out Layer lines w0.2: -23,-3.95 -12.619,-3.95 -11.447,-0.729 ; -11.444,-0.73 cw(c-10.34,-1.2) -10.34,0 9.898,0 ; 9.898,0.002 cw(c9.898,-1.198) 11.002,-0.728 12.6,-5.05 23,-5.05
"MKDSO2.5 HV/3R-7.5" [mil]
  round 100 hole 56: 1(0,0) 2(-362.2,0) 3(-0.04,-393.74)
  silkscreen extent -398,-484 711,439
"MKDSO 2.5/4-L" [mil]
  round 100 hole 56: 1(0,98.43) 2(0,-98.43) 3(0,295.28) 4(0,-295.28)
  silkscreen extent -547,-366 71,478
R1608(0603) [mm] "Chip Resistor, Body 1.6x0.8mm, IPC Medium Density"
  rect 1x1 smd: 1(0.8,0) 2(-0.8,0)
  Top Layer pour cut-out: -0.3,0.75 0.3,0.75 0.3,-0.75 -0.3,-0.75
  silkscreen extent -1.66,-0.86 1.66,0.86, body extent -0.87,-0.48 0.87,0.48, height 0.85
R3216(1206) [mm] "Chip Resistor, Body 3.2x1.6mm, IPC Medium Density"
  rect 1.3x1.8 smd: 1(1.45,0) 2(-1.45,0)
  Top Layer pour cut-out: -0.8,1.15 0.8,1.15 0.8,-1.15 -0.8,-1.15
  silkscreen extent -2.46,-1.26 2.46,1.26, body extent -1.7,-0.9 1.7,0.9, height 1.35
R4532(1812) [mm] "Chip Resistor, Body 4.5x3.2mm, IPC Medium Density"
  rect 1.6x3.4 smd: 1(2,0) 2(-2,0)
  Top Layer pour cut-out: 1.2,-1.95 -1.2,-1.95 -1.2,1.95 1.2,1.95
  silkscreen extent -3.16,-2.06 3.16,2.06, body extent -2.4,-1.7 2.4,1.7, height 0.71
RJ45-LED [mm]
  round 3.5 hole 3.5: 0(-9.9,6.035) 0(1.16,6.035)
  oct 1.5x2 hole 1: 1(0.01,-0.005) 9(2.185,10.935) 12(-11.065,10.935)
  oval 1.5x2 hole 1: 2(-1.26,-2.545) 3(-2.53,-0.005) 4(-3.8,-2.545) 5(-5.07,-0.005) 6(-6.34,-2.545) 7(-7.61,-0.005) 8(-8.88,-2.545) 10(-0.355,10.935) 11(-8.525,10.935)
  oval 2x2.4 hole 1.5: 13(3.58,3.085) 14(-12.42,3.085)
  silkscreen extent -12.42,-4.02 3.58,16.98
SIP8 [mm] "SIP; 8 Round Pins; Body 22x9.5mm; Pitch 2.54 mm"
  rect 1.65x1.65 hole 1: 1(-8.89,2.54)
  round 1.65 hole 1: 2(-6.35,2.54) 3(-3.81,2.54) 5(1.27,2.54) 6(3.81,2.54) 7(6.35,2.54) 8(8.89,2.54)
  silkscreen extent -11,-4.1 11,5.93, body extent -11,-4.1 11,5.4, height 12
SO8_M [mm] "8-Pin Small Outline Integrated Circuit 1.27 mm Pitch, IPC Low Density"
  oval 2.5x0.7 smd: 1(-2.45,1.905) 2(-2.45,0.635) 3(-2.45,-0.635) 4(-2.45,-1.905) 5(2.45,-1.905) 6(2.45,-0.635) 7(2.45,0.635) 8(2.45,1.905)
  silkscreen extent -2.57,-2.5 0.8,2.93, body extent -2,-2.5 2,2.5, height 1.75
SOD123 [mm] "SOD-123; 2 Leads; Body 2.7 x 1.6 mm, (LxW)"
  rect 1.7x1.4 smd: 1(-1.65,0) 2(1.65,0)
  Top Layer pour cut-out: -0.8,0.95 -0.8,-0.95 0.8,-0.95 0.8,0.95
  silkscreen extent -3.06,-1.15 3.06,1.15, body extent -1.85,-0.91 1.85,0.9, height 1.35
SOD323 [mm] "SOD-323; 2 Leads; Body 2.5 x 1.3 mm, (LxW)"
  rect 1x1 smd: 1(-1.25,0) 2(1.25,0)
  Top Layer pour cut-out: -0.75,0.75 -0.75,-0.75 0.75,-0.75 0.75,0.75
  silkscreen extent -2.31,-0.86 2.31,0.86, body extent -1.25,-0.75 1.25,0.75, height 1.35
SOIC8_M [mm] "SOIC, 8-Leads, Body 5.4x5.4mm (max), Pitch 1.27mm, IPC Low Density"
  oval 3.4x0.7 smd: 1(-3,1.905) 2(-3,0.635) 3(-3,-0.635) 4(-3,-1.905) 5(3,-1.905) 6(3,-0.635) 7(3,0.635) 8(3,1.905)
  silkscreen extent -3.72,-2.7 0.9,2.93, body extent -2.69,-2.69 2.69,2.69, height 2.16
SOT23-3_N [mm] "SOT23, 3-Leads, Body 2.9x1.3mm, Pitch 0.95mm, Lead Span 2.3mm, IPC Medium Density"
  rect 1.3x0.6 smd: 1(1.05,-0.95) 2(1.05,0.95) 3(-1.05,0)
  Top Layer pour cut-out: 1.95,-0.65 -0.4,-0.65 -0.4,0.65 1.95,0.65
  silkscreen extent -0.7,-1.92 1.17,1.5, body extent -0.7,-1.5 0.7,1.5, height 1.2
SOT23-5_N [mm] "SOT23, 5-Leads, Body 2.9x1.6mm, Pitch 0.95mm, Lead Span 2.8mm, IPC Medium Density"
  rect 1.1x0.6 smd: 1(-1.2,0.95) 2(-1.2,0) 3(-1.2,-0.95) 4(1.2,-0.95) 5(1.2,0.95)
  silkscreen extent -1.33,-1.55 0.25,1.95, body extent -0.9,-1.55 0.9,1.55, height 1.45
TQFP100_N [mm] "100-Pin Thin Quad Flat Pack 0.5 mm Pitch, IPC Medium Density"
  oval 1.8x0.3 smd: 1(-7.55,6) 2(-7.55,5.5) 3(-7.55,5) 4(-7.55,4.5) 5(-7.55,4) 6(-7.55,3.5) 7(-7.55,3) 8(-7.55,2.5) 9(-7.55,2) 10(-7.55,1.5) 11(-7.55,1) 12(-7.55,0.5) 13(-7.55,0) 14(-7.55,-0.5) 15(-7.55,-1) 16(-7.55,-1.5) 17(-7.55,-2) 18(-7.55,-2.5) 19(-7.55,-3) 20(-7.55,-3.5) 21(-7.55,-4) 22(-7.55,-4.5) 23(-7.55,-5) 24(-7.55,-5.5) 25(-7.55,-6) 51(7.55,-6) 52(7.55,-5.5) 53(7.55,-5) 54(7.55,-4.5) 55(7.55,-4) 56(7.55,-3.5) 57(7.55,-3) 58(7.55,-2.5) 59(7.55,-2) 60(7.55,-1.5) 61(7.55,-1) 62(7.55,-0.5) 63(7.55,0) 64(7.55,0.5) 65(7.55,1) 66(7.55,1.5) 67(7.55,2) 68(7.55,2.5) 69(7.55,3) 70(7.55,3.5) 71(7.55,4) 72(7.55,4.5) 73(7.55,5) 74(7.55,5.5) 75(7.55,6)
  oval 0.3x1.8 smd: 26(-6,-7.55) 27(-5.5,-7.55) 28(-5,-7.55) 29(-4.5,-7.55) 30(-4,-7.55) 31(-3.5,-7.55) 32(-3,-7.55) 33(-2.5,-7.55) 34(-2,-7.55) 35(-1.5,-7.55) 36(-1,-7.55) 37(-0.5,-7.55) 38(0,-7.55) 39(0.5,-7.55) 40(1,-7.55) 41(1.5,-7.55) 42(2,-7.55) 43(2.5,-7.55) 44(3,-7.55) 45(3.5,-7.55) 46(4,-7.55) 47(4.5,-7.55) 48(5,-7.55) 49(5.5,-7.55) 50(6,-7.55) 76(6,7.55) 77(5.5,7.55) 78(5,7.55) 79(4.5,7.55) 80(4,7.55) 81(3.5,7.55) 82(3,7.55) 83(2.5,7.55) 84(2,7.55) 85(1.5,7.55) 86(1,7.55) 87(0.5,7.55) 88(0,7.55) 89(-0.5,7.55) 90(-1,7.55) 91(-1.5,7.55) 92(-2,7.55) 93(-2.5,7.55) 94(-3,7.55) 95(-3.5,7.55) 96(-4,7.55) 97(-4.5,7.55) 98(-5,7.55) 99(-5.5,7.55) 100(-6,7.55)
  silkscreen extent -7.67,-6.25 6.25,6.83, body extent -7,-7 7,7, height 1.6
XTAL-3225 [mm]
  rect 1.4x1.15 smd: 1(-1.108,-0.802) 2(1.092,-0.802) 3(1.092,0.798) 4(-1.108,0.798)
  Top Layer pour cut-out: -0.41,1.62 0.39,1.62 0.39,0.22 2.04,0.22 2.04,-0.23 0.39,-0.23 0.39,-1.63 -0.41,-1.63 -0.41,-0.23 -2.06,-0.23 -2.06,0.22 -0.41,0.22
  silkscreen extent -1.96,-1.5 1.94,1.5

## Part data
C1 C2 C6 C8 C9 C10 C12 C14 C15 C19 C21 C22 C23 C24 C26 C27 C28 C29 C30 C31 C32 C33 C34 C35 C36 C38 C39 C40 C41 C42 C43 C44 C45 C46 C47 C48 C49 C50 C51 C52 C53 C54 C55 C56 C57 C58 C59 C60 C61 C62 C63 C64 C66 C69 C70 C73 C74 C75: library part CAP, "Capacitor"
C3 C4 C11 C16 C17 C65 C67 C68 C71 C72: library part "CAPACITOR POL", "CA45-?V?uF ABCD 16V10UF[A型3210]16V22UF(B型1210) 16V47UF(C型1812)"
C13 C25 C37: library part "Cap Pol2", "Polarized Capacitor (Axial)"
D2 D5: "Typical INFRARED GaAs LED"
D3: library part Diode, "Default Diode"
D4: library part "D Zener", "Zener Diode"
F3: library part FUSE1, "Fuse"
J1: library part "Header 6X2", "Header, 6-Pin, Dual row"
J3: "Header, 3-Pin"
J5: "Receptacle Assembly, 9 Position, Right Angle"
L1 L3 L4 L5 L6 L7: library part Inductor, "Inductor"
R1 R2 R3 R5 R42 R43 R44 R45 R46 R47 R48 R49 R69 R70 R71: library part R
R4: library part "Res Varistor", "Varistor (Voltage-Sensitive Resistor)"
R6 R7 R8 R9 R10 R11 R12 R13 R14 R15 R16 R17 R18 R19 R20 R21 R22 R23 R24 R25 R26 R27 R28 R29 R30 R31 R32 R33 R34 R35 R36 R37 R38 R39 R40 R41 R50 R51 R52 R53 R54 R55 R56 R57 R58 R59 R60 R61 R62 R63 R64 R65 R66 R67 R68 R75: library part "Res Semi", "Semiconductor Resistor"
SW2: "Switch"
U1: "ARM Cortex-M4 32b MCU+FPU, 210DMIP, 1024 kB Flash, 192+4 kB RAM, Camera, 82 I/Os, 100-pin LQFP, -40 to +85癈, Tray"
U2: library part MAX6520EUR-T, "3-Terminal, 1.2V Voltage Reference"
U3 U4: library part WRA_S-1WR2
U5: library part DP83848CVV
U6 U9 U12: library part HCPL-060
U10: library part 25AA640A-I/SN, "64K SPI Bus Serial EEPROM, 8-Pin SOIC, Industrial Temperature"
U11: library part MAX485ESA, "Low-Power, Slew-Rate-Limited RS-485/RS-422 Transceiver"
X1 X2: library part CRYSTAL

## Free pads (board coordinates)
  round 30 on Plane1: 1(3098.43,2763.78) 2(3421.26,2763.78)

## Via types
v1: diameter 26, hole 13, Top Layer to Bottom Layer, tented both sides, 363 vias
v2: diameter 26, hole 13, Top Layer to Bottom Layer, 4 vias
v3: diameter 27.56, hole 27.56, Top Layer to Bottom Layer, tented both sides, 2 vias

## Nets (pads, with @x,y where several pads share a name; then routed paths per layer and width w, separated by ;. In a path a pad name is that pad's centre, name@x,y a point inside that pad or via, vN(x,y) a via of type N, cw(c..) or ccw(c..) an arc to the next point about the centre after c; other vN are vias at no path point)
5T1: U12.1
5T2: U12.4
5T3: J5.2
5T4: J5.7
5T5: J5.4
5T6: J5.9
5T7: U4.5
BOOT0: R2.1 R42.2 U1.94 | length 1649.8
  Top Layer w10: v1(1578.74,1944.88) 1594.77,1960.91 2010.52,1960.91 2073.74,2024.13 2104.84,2024.13 2137.4,2056.69 2252.27,2056.69 2263.3,2067.72 2368.8,2067.72 2369.3,2067.21 2375.05,2067.21 2425.72,2016.54 v1@2537.8,2016.54 ; 2498.7,2016.54 ccw(c2498.7,2063.27) v1@2531.74,2030.22 ; 2522.84,2016.54 ccw(c2522.84,2039.13) v1@2538.82,2023.15
  Bottom Layer w8: v1@2531.04,2030.93 ccw(c2515.67,2046.3) 2537.4,2046.3 ccw(c2559.13,2046.29) v1@2543.77,2030.93 ; v1@2537.4,2024.41 2537.4,2059.41 2567.93,2089.95 2647.03,2089.95 U1.94@2647.64,2090.55 ; 2612.05,2089.95 ccw(c2612.05,2096.61) U1.94@2616.76,2091.9
  Bottom Layer w10: R2.1@1568.36,1977.81 cw(c1543.29,1952.74) 1578.74,1952.74 cw(c1614.19,1952.74) R2.1@1589.12,1977.81 ; R2.1@1568.36,1998.57 ccw(c1543.29,2023.64) 1578.74,2023.64 ccw(c1614.19,2023.64) R2.1@1589.12,1998.57 ; R42.2@1568.36,2103.79 cw(c1543.29,2078.72) 1578.74,2078.72 cw(c1614.19,2078.72) R42.2@1589.12,2103.79 ; v1@1573.08,1950.54 ccw(c1559.43,1964.2) 1578.74,1964.2 ccw(c1598.05,1964.2) v1@1584.4,1950.54 ; v1(1578.74,1944.88) R42.2@1578.74,2114.17
  other v1: 2537.4,2024.57
BOOT_0: J1.5 R42.1 | length 458.7
  Bottom Layer w10: R42.1@1641.73,2114.17 1737.01,2209.45 J1.5@1759.84,2209.45 ; R42.1@1641.73,2128.86 ccw(c1641.73,2164.31) 1666.8,2139.24 ccw(c1691.87,2114.17) R42.1@1656.42,2114.17 ; 1678.99,2151.43 cw(c1759.84,2070.58) J1.5@1759.84,2184.92 ; 1696.06,2168.5 cw(c1759.84,2104.72) J1.5@1759.84,2194.92 ; 1713.13,2185.57 cw(c1759.84,2138.86) J1.5@1759.84,2204.92 ; 1730.2,2202.64 cw(c1759.84,2173.01) J1.5@1759.84,2214.92
DE: R60.2 U7.4 U11.3 | length 1425.4
  Top Layer w10: v1@2263.35,3094.52 cw(c2279.21,3078.66) 2279.21,3101.09 ; v1@2264.87,3101.09 2453.63,3101.09 2534.76,3019.97 2570.59,3019.97 2586.62,3003.94 v1(2641.73,3003.94) ; v1@2270.42,3087.45 cw(c2303.35,3054.52) 2303.35,3101.09 ; v1@2636.08,2998.28 ccw(c2622.42,2984.62) 2622.42,3003.94 ccw(c2622.42,3023.25) v1@2636.08,3009.59
  Bottom Layer w10: v1@2256.75,3094.09 cw(c2235.02,3094.09) 2250.38,3078.73 cw(c2265.75,3063.37) v1@2265.75,3085.09 ; v1@2264.76,3092.91 2248.78,3076.93 2248.78,2934.29 2263.19,2919.88 U11.3@2332.68,2919.88 ; U11.3@2291.04,2913.67 ccw(c2276.05,2898.69) 2276.05,2919.88 ccw(c2276.05,2941.08) U11.3@2291.04,2926.09 ; R60.2@2503.94,2874.02 2559.06,2929.13 2559.06,2952.75 2610.24,3003.94 v1(2641.73,3003.94) 2665.35,2980.32 2748.03,2980.32 2756.97,2971.38 2756.97,2890.83 U7.4@2728.35,2862.2 ; R60.2@2503.94,2889.09 ccw(c2503.94,2925.5) 2529.68,2899.76 ; R60.2@2518.62,2874.41 cw(c2553.12,2874.41) 2528.73,2898.81 ; v1@2636.08,2998.28 ccw(c2622.42,2984.62) 2622.42,3003.94 ccw(c2622.42,3023.25) v1@2636.08,3009.59 ; v1@2640.55,2996.12 cw(c2640.55,2974.39) 2655.91,2989.75 cw(c2671.28,3005.12) v1@2649.55,3005.12 ; U7.4@2730.31,2870.89 ccw(c2730.31,2887.09) U7.4@2741.77,2875.63 ; U7.4@2737.13,2864.07 cw(c2753.81,2864.07) U7.4@2742.01,2875.87
  other v1: 2264.76,3093.11
DE#: R53.1 U6.6 U7.1 | length 1152.4
  Top Layer w10: U6.6@2184.15,2889.46 cw(c2169.16,2874.47) 2190.35,2874.47 cw(c2211.55,2874.47) U6.6@2196.56,2889.46 ; U6.6@2190.35,2931.1 2190.35,2868.7 2201.08,2857.98 2873.73,2857.98 2885.83,2870.08 v1@2885.83,2937.01 ; v1@2880.17,2933.32 cw(c2866.51,2919.66) 2885.83,2919.66 cw(c2905.14,2919.66) v1@2891.48,2933.32
  Bottom Layer w10: U7.1@2814.96,2938.88 R53.1@2927.26,2938.88 ; U7.1@2829.62,2934.06 cw(c2841.25,2922.43) 2841.25,2938.88 cw(c2841.25,2955.32) U7.1@2829.62,2943.69 ; 2866.28,2938.88 ccw(c2866.28,2958.53) v1@2880.17,2944.63 ; 2866.75,2938.88 cw(c2866.75,2919.9) v1@2880.17,2933.32 ; v1@2890.12,2938.88 cw(c2890.12,2898.38) R53.1@2918.75,2927.02 ; v1@2891.48,2933.32 cw(c2904.9,2919.9) 2904.9,2938.88 ; v1@2891.48,2944.63 ccw(c2905.38,2958.53) 2905.38,2938.88 ; v1@2897.25,2938.88 ccw(c2897.25,2969.29) R53.1@2918.75,2947.79
  other v1: 2885.83,2938.98
DP-A: J5.3 R63.1 U11.6 | length 1331.5
  Bottom Layer w10: U11.6@2098.12,2913.67 ccw(c2083.14,2898.69) 2083.14,2919.88 ccw(c2083.14,2941.08) U11.6@2098.12,2926.09 ; U11.6@2139.76,2919.88 2076.18,2919.88 2055.86,2940.2 2055.86,3132.47 2084.81,3161.42 2364.17,3161.42 J5.3@2442.91,3240.16 ; R63.1@2381.89,3418.39 cw(c2381.89,3382.93) 2406.96,3408 cw(c2432.03,3433.07) R63.1@2396.57,3433.07 ; R63.1@2381.89,3433.07 2440.94,3374.02 J5.3@2440.94,3236.22 ; 2383.29,3180.53 cw(c2442.74,3121.07) J5.3@2442.74,3205.16 ; 2400.36,3197.6 cw(c2442.74,3155.21) J5.3@2442.74,3215.16 ; 2404.6,3201.84 ccw(c2375.29,3231.16) J5.3@2416.74,3231.16 ; J5.3@2424.36,3267.54 ccw(c2384.31,3307.59) 2440.94,3307.59 ; J5.3@2431.43,3260.47 ccw(c2408.45,3283.45) 2440.94,3283.45 ; 2440.94,3292.12 ccw(c2485.71,3292.12) J5.3@2454.06,3260.47 ; 2440.94,3316.27 ccw(c2509.85,3316.27) J5.3@2461.13,3267.54
DP-B: J5.8 R67.2 U11.7 | length 1272.8
  Bottom Layer w10: 2080.82,2983.16 ccw(c2095.21,2997.55) U11.7@2101.58,2978.22 ; U11.7@2139.76,2969.88 2094.09,2969.88 2075.7,2988.28 2075.7,3066.65 2075.71,3071.14 2075.7,3094.21 2075.71,3098.7 2075.7,3124.25 2093.03,3141.57 2385.12,3141.57 2420.71,3177.17 2468.5,3177.17 2496.06,3204.72 2496.06,3405.51 ; J5.8@2479.36,3312.77 cw(c2439.03,3272.44) 2496.06,3272.44 ; J5.8@2479.91,3368.08 ccw(c2444.62,3405.51) 2496.06,3405.51 ; J5.8@2486.43,3319.84 cw(c2463.17,3296.58) 2496.06,3296.58 ; J5.8@2486.77,3360.8 ccw(c2466.46,3382.34) 2496.06,3382.34 ; 2496.06,3264.33 cw(c2564.57,3264.33) J5.8@2516.13,3312.77 ; 2496.06,3288.48 cw(c2540.42,3288.48) J5.8@2509.06,3319.84 ; 2496.06,3385.15 ccw(c2525.54,3385.15) J5.8@2507.52,3361.82 ; R67.2@2508.94,3433.07 cw(c2473.48,3433.07) 2498.55,3408 cw(c2523.62,3382.93) R67.2@2523.62,3418.39 ; J5.8@2513.63,3369.73 cw(c2541.26,3405.51) 2496.06,3405.51 ; R67.2@2523.62,3433.07 2496.06,3405.51
ETH_RD+: J4.3 R24.1 U5.14 | length 1342.5
  Bottom Layer w8: U5.14@2905.51,2401.57 2905.51,2547.74 2968.01,2610.24 3077.62,2610.24 3097.31,2629.92 3157.48,2629.92 R24.1@3192.91,2665.35 3157.48,2700.79 3157.48,2797.38 3172.81,2812.71 3332.39,2812.71 3393.7,2874.02 3393.7,2960.63 3425.2,2992.13 3429.13,2996.06 3448.82,2996.06 J4.3@3496.06,3043.31 ; R24.1@3192.91,2649.67 ccw(c3192.91,2611.8) 3166.14,2638.58 ccw(c3139.36,2665.35) 3177.23,2665.35 ccw(c3139.36,2665.35) 3166.14,2692.13 ccw(c3192.91,2718.91) R24.1@3192.91,2681.04 ; 3451.15,2998.4 cw(c3486.33,2963.22) J4.3@3495.57,3012.1 ; 3461.86,3009.1 cw(c3489.74,2981.23) J4.3@3497.06,3019.97 ; 3467.09,3014.33 ccw(c3452.1,3029.33) J4.3@3473.3,3029.33
ETH_RD-: J4.6 R31.1 U5.13 | length 1402.4
  Bottom Layer w8: U5.13@2885.83,2401.57 2885.83,2553.51 2960.56,2628.24 3061.31,2628.24 R31.1@3098.43,2665.35 3137.8,2704.72 3137.8,2803.15 3165.35,2830.71 3165.35,2870.08 3173.23,2877.95 3185.04,2877.95 3192.91,2870.08 3192.91,2838.58 3200.79,2830.71 3212.6,2830.71 3220.47,2838.58 3220.47,2870.08 3228.35,2877.95 3240.16,2877.95 3248.03,2870.08 3248.03,2838.58 3255.91,2830.71 3267.72,2830.71 3275.59,2838.58 3275.59,2874.02 3283.46,2881.89 3295.28,2881.89 3303.15,2874.02 3303.15,2838.58 3311.02,2830.71 3324.94,2830.71 3348.43,2854.2 J4.6@3348.43,2937.01 ; R31.1@3082.74,2665.35 cw(c3044.87,2665.35) 3071.65,2638.58 cw(c3098.43,2611.8) R31.1@3098.43,2649.67 ; R31.1@3098.43,2681.04 ccw(c3098.43,2718.91) 3125.2,2692.13 ccw(c3151.98,2665.35) R31.1@3114.11,2665.35 ; J4.6@3330.78,2911.28 cw(c3288.18,2868.67) 3348.43,2868.67 ; J4.6@3336.44,2916.93 cw(c3307.49,2887.99) 3348.43,2887.99 ; 3348.43,2866.72 cw(c3411.43,2866.72) J4.6@3366.88,2911.28 ; 3348.43,2886.04 cw(c3392.12,2886.04) J4.6@3361.22,2916.93
ETH_TD+: J4.1 R15.1 U5.17 | length 1476.5
  Bottom Layer w8: U5.17@2964.57,2401.57 2964.57,2527.56 2993.56,2556.55 3099.86,2556.55 3119.54,2576.24 3221.41,2576.24 3245.7,2600.52 3296.25,2600.52 3325.65,2629.92 3385.83,2629.92 R15.1@3421.26,2665.35 ; R15.1@3417.32,2669.29 3384.14,2702.47 3384.14,2768.13 3409.03,2793.02 3548.93,2793.02 3568.88,2812.98 3568.88,2879.91 3598.43,2909.45 J4.1@3598.43,3039.37 ; R15.1@3421.26,2649.67 ccw(c3421.26,2611.8) 3394.48,2638.58 ccw(c3367.71,2665.35) 3405.57,2665.35 ccw(c3367.71,2665.35) 3394.48,2692.13 ccw(c3421.26,2718.91) R15.1@3421.26,2681.04 ; J4.1@3580.78,3011.28 cw(c3538.17,2968.67) 3598.43,2968.67 ; J4.1@3586.43,3016.93 cw(c3557.49,2987.99) 3598.43,2987.99 ; 3598.43,2966.73 cw(c3661.43,2966.73) J4.1@3616.88,3011.28 ; 3598.43,2986.04 cw(c3642.12,2986.04) J4.1@3611.22,3016.93
ETH_TD-: J4.2 R20.1 U5.16 | length 1586.9
  Bottom Layer w8: U5.16@2944.88,2401.57 2944.88,2533.33 2986.1,2574.55 3092.4,2574.55 3112.09,2594.24 3213.96,2594.24 3238.24,2618.52 3279.94,2618.52 R20.1@3326.77,2665.35 3366.14,2704.72 3366.14,2775.59 3401.57,2811.02 3429.13,2811.02 3437.01,2818.9 3437.01,2842.52 3444.88,2850.39 3456.69,2850.39 3464.57,2842.52 3464.57,2818.9 3472.44,2811.02 3484.25,2811.02 3492.13,2818.9 3492.13,2881.89 3500.97,2890.74 3510.84,2890.74 3519.69,2881.89 3519.69,2818.9 3527.56,2811.02 3539.37,2811.02 3547.24,2818.9 J4.2@3547.24,2933.07 ; R20.1@3311.09,2665.35 cw(c3273.22,2665.35) 3299.99,2638.58 cw(c3326.77,2611.8) R20.1@3326.77,2649.67 ; R20.1@3326.77,2681.04 ccw(c3326.77,2718.91) 3353.55,2692.13 ccw(c3380.32,2665.35) R20.1@3342.46,2665.35 ; J4.2@3530.78,2911.28 cw(c3491.02,2871.52) 3547.24,2871.52 ; J4.2@3534.32,2908.32 cw(c3517.32,2883.7) 3547.24,2883.7 cw(c3573.67,2883.7) J4.2@3561.03,2906.91 ; J4.2@3536.43,2916.93 cw(c3510.34,2890.84) 3547.24,2890.84 ; J4.2@3538.87,2914.9 cw(c3527.85,2898.94) 3547.24,2898.94 ; 3547.24,2863.87 cw(c3614.28,2863.87) J4.2@3566.88,2911.28 ; 3547.24,2883.19 cw(c3594.97,2883.19) J4.2@3561.22,2916.93 ; 3547.24,2897.16 cw(c3566.34,2897.16) J4.2@3557.21,2913.93
GND: C1.2 C2.2 C3.2 C4.2 C6.1 C8.1 C13.2 C14.1 C27.2 C28.2 C29.2 C30.1 C31.1 C32.1 C33.1 C34.1 C35.1 C36.1 C37.2 C38.2 C39.2 C40.2 C41.2 C42.2 C43.2 C44.2 C45.2 C46.2 C47.2 C48.2 C49.2 C50.2 C51.1 C52.1 C53.1 C54.1 C55.2 C56.2 C57.1 C60.2 C64.2 C71.2 C72.2 C73.1 C74.1 C75.1 J1.1 J1.2 J4.8 R2.2 R3.2 R40.2 R41.2 R44.1 R49.1 R52.1 R69.1 R75.2 U1.10 U1.20 U1.27 U1.74 U1.99 U2.1 U3.7 U5.15 U5.19 U5.35 U5.36 U5.47 U10.4 U12.5 X2.2 X2.4 | length 2018.3
  Bottom Layer w8: v1@2212.6,1850.39 U1.20@2212.6,1911.42 ; 2867.98,2417.32 2867.98,2560.9 2972.44,2665.35 C29.2@3031.5,2665.35 ; U5.15@2925.2,2401.57 2925.2,2542.19 2975.4,2592.39 3085.01,2592.39 3104.7,2612.08 3206.57,2612.08 C28.2@3259.84,2665.35 ; U5.19@3003.94,2397.24 3003.94,2528.74 3013.91,2538.71 3107.25,2538.71 3126.93,2558.39 3228.8,2558.39 3253.09,2582.68 3307.09,2582.68 3332.68,2608.27 3466.54,2608.27 ; C28.2@3244.16,2665.35 cw(c3206.29,2665.35) 3233.07,2638.58 cw(c3259.84,2611.8) C28.2@3259.84,2649.67
  Bottom Layer w10: 3466.54,2608.27 3522.72,2664.45 3522.72,2740.16 3587.73,2805.17 3587.73,2868.24 3647.1,2927.61
  other v1: 1535.43,1535.43 1594.49,1535.43 1653.54,1535.43 1712.6,1535.43 2094.49,1562.99 2094.49,1586.61 1535.43,1594.49 2407.87,1609.06 2272.64,1634.84 1570.87,1641.73 1669.29,1649.61 1755.91,1649.61 1535.43,1653.54 2385.83,1704.72 2476.38,1704.72 2283.46,1708.66 1535.43,1712.6 2497.24,1720.47 2104.33,1729.33 2171.26,1729.33 2497.24,1746.85 3381.89,1759.84 1535.43,1771.65 3381.89,1811.02 1791.34,1838.58 2212.6,1849.61 3370.08,1858.27 3421.26,1858.27 1858.27,1897.64 3174.21,1902.56 1535.43,1909.45 3179.13,1926.18 1822.83,1933.07 1889.76,1933.07 2003.94,1933.07 2631.5,1945.28 2345.87,1972.83 2889.76,2011.81 1669.29,2023.62 2747.64,2031.5 3397.64,2043.31 1535.43,2047.24 3397.64,2086.61 3204.72,2092.52 1929.13,2094.49 3355.32,2104.33 3204.72,2117.13 1535.43,2165.35 1547.24,2212.6 1535.43,2303.15 2928.35,2340.55 1547.24,2342.52 2303.15,2389.76 2728.35,2397.64 1551.18,2407.48 3003.94,2464.57 1535.43,2468.5 2677.17,2523.62 1637.8,2535.43 3318.9,2555.12 1700.79,2574.8 3318.9,2580.71 2728.35,2602.36 1791.34,2633.86 2519.68,2661.42 2543.31,2661.42 2998.03,2665.35 2714.57,2676.18 2582.68,2677.17 1968.5,2700.79 2342.52,2700.79 2012.8,2745.08 3522.64,2765.75 2055.12,2788.39 2357.28,2798.23 2674.21,2798.23 2717.52,2798.23 2879.92,2798.23 2954.72,2799.21 3027.56,2799.21 3078.74,2846.46 3602.36,2846.46 3122.05,2893.7 3649.61,2893.7 3696.85,2940.94 3122.05,2972.44 3744.09,3011.81 3122.05,3051.18 3681.1,3078.74 3637.8,3141.73 3216.54,3145.67 3582.68,3169.29 3354.33,3251.97 3500,3251.97 3429.13,3259.84 3330.71,3275.59 3519.68,3279.53 3429.13,3311.02
GNDD: C15.1 C16.2 C17.2 C19.1 C21.1 C25.2 C58.2 C59.2 C61.1 C62.2 C63.2 C67.2 C68.2 C69.1 C70.1 J5.5 R5.2 R60.1 R62.2 R67.1 R70.1 U4.7 U6.5 U7.3 U8.3 U9.5 U11.5
  other v1: 4007.87,1488.19 4055.12,1488.19 4255.91,1488.19 4350.39,1488.19 4059.06,1529.53 4059.06,1556.1 4350.39,1566.93 3984.25,1610.24 3925.2,1633.86 3854.33,1637.8 4297.24,1639.76 4322.83,1639.76 4348.42,1639.76 3854.33,1700.79 3854.33,1748.03 3901.57,1795.28 4349.41,1875 4350.39,1996.06 4099.41,2007.87 4125.98,2007.87 4314.96,2039.37 4084.65,2044.29 4084.65,2070.87 4169.29,2072.83 4267.72,2072.83 4350.39,2072.83 2055.12,2865.16 2037.4,2882.87 2649.6,2885.82 2578.74,2886.81 2019.69,2900.59 2001.97,2918.31 1984.25,2936.02 2527.56,2992.13 2559.06,2992.13 2870.08,3003.94 2220.47,3005.91 3051.18,3027.56 3051.18,3055.12 2322.83,3059.06 3006.89,3098.43 2234.25,3113.19 2989.17,3117.13 2419.29,3128.94 2870.08,3133.86 2971.46,3134.84 2921.26,3136.81 2946.85,3136.81 2653.54,3153.54 2677.17,3153.54 2826.77,3173.23 2292.91,3189.37 2781.5,3251.97 2780.51,3307.09 2204.72,3338.58 2338.58,3385.83 2204.72,3397.64 2204.72,3456.69 2248.03,3500 2311.02,3500 2362.2,3500 2413.39,3500 2468.5,3500 2519.68,3500 2574.8,3500 2629.92,3500 2681.1,3500
GNDE: C14.2 C15.2 C26.2 J3.2 J4.0 J4.13 J4.14 J5.1 J5.10 J5.11 R69.2 R70.2 R71.2 Temp1.6 | length 11291.4
  Top Layer w19.68: J5.10@1942.11,3284.45 ccw(c2034.94,3349.67) 2034.94,3236.22 ; J5.10@1950.24,3339.28 ccw(c1950.24,3451.58) 2029.65,3372.17 ; J5.10@1950.24,3358.96 ccw(c1950.24,3518.79) 2063.25,3405.77 ; J5.10@1950.24,3378.65 ccw(c1950.24,3585.99) 2096.86,3439.38 ; J5.10@1958.22,3295.76 ccw(c2072.83,3376.3) 2072.83,3236.22 ; J5.10@1974.33,3307.08 ccw(c2110.72,3402.93) 2110.72,3236.22 ; J5.10@1990.43,3318.4 ccw(c2148.62,3429.55) 2148.62,3236.22 ; J5.10@1999.36,3290.16 cw(c2124.24,3290.16) 2035.94,3378.46 ; J5.10@2006.54,3329.72 ccw(c2186.51,3456.18) 2186.51,3236.22 ; J5.10@2012.81,3227.59 cw(c2033.66,3206.74) 2033.66,3236.22 ; J5.10@2019.05,3290.16 cw(c2191.45,3290.16) 2069.54,3412.06 ; J5.10@2022.65,3341.03 ccw(c2224.4,3482.8) 2224.4,3236.22 1893.7,3236.22 2220.47,3562.99 2707.29,3562.99 J4.14@3109.46,3160.82 ; J5.10@2038.73,3290.16 cw(c2258.66,3290.16) 2103.15,3445.67 ; 2171.07,3236.22 ccw(c2171.07,3290.5) J5.1@2209.45,3252.12 ; 2175.59,3236.22 cw(c2175.59,3188.34) J5.1@2209.45,3222.2 ; 2751.02,3519.26 cw(c2521.91,3290.16) J5.11@2845.92,3290.16 ; 2784.62,3485.66 cw(c2589.12,3290.16) J5.11@2865.6,3290.16 ; 2818.23,3452.05 cw(c2656.33,3290.16) J5.11@2885.29,3290.16 ; 2851.83,3418.45 cw(c2723.54,3290.16) J5.11@2904.97,3290.16 ; 2861.39,3408.89 ccw(c2934.41,3481.91) J5.11@2934.41,3378.65 ; 2885.44,3384.85 cw(c2790.75,3290.16) J5.11@2924.66,3290.16 ; J5.11@2885.63,3338.94 cw(c2979.81,3244.76) 2979.81,3377.95 ; J5.11@2899.54,3325.02 cw(c3027.33,3197.23) 3027.33,3377.95 ; J5.11@2913.46,3311.1 cw(c3074.86,3149.71) 3074.86,3377.95 ; J5.11@2925.2,3377.95 J3.2@3850.39,3377.95 ; J5.11@2927.38,3297.18 cw(c3122.38,3102.19) 3122.38,3377.95 ; J5.11@2938.01,3260.94 cw(c2954.05,3130.84) 3046.75,3223.53 ; J5.11@2940.42,3241.41 cw(c2960.32,3080.06) 3075.27,3195.01 ; J5.11@2941.3,3283.26 cw(c3169.9,3054.66) 3169.9,3377.95 ; J5.11@2942.83,3221.87 cw(c2966.58,3029.28) J4.14@3103.79,3166.49 ; J5.11@2955.22,3269.34 cw(c3217.43,3007.14) 3217.43,3377.95 ; J5.11@3022.9,3290.16 ccw(c3126.16,3290.16) 3053.14,3217.14 ; 3045.61,3224.67 ccw(c3109.46,3288.52) J4.14@3109.46,3198.22 ; 3064.62,3205.66 cw(c3027.66,3168.7) J4.14@3079.93,3168.7 ; 3705.66,3377.95 cw(c3705.66,3209.85) J3.2@3824.53,3328.72 ; J4.13@3739.38,3123.42 cw(c3739.38,3029.82) 3805.57,3096.01 ; J4.13@3739.38,3143.11 cw(c3739.38,3097.02) 3771.97,3129.61 ; J4.13@3739.38,3160.82 3739.38,3192.14 J3.2@3878.64,3331.4 ; J4.13@3740.16,3161.42 3811.02,3090.55 3811.02,2964.57 3528.18,2681.72 3427.09,2681.72 3381.89,2636.53 3381.89,2198.12 3424.5,2155.51 3504.64,2155.51 3522.35,2173.23 3709.65,2173.23 3742.72,2206.3 3742.72,2259.43 3790.57,2307.28 3858.25,2307.28 3909.45,2256.08 3909.45,1895.1 3821.44,1807.09 Temp1.6@3763.39,1807.09 ; J4.13@3749.22,3168.7 cw(c3829.57,3168.7) 3772.76,3225.51 ; 3753.19,3377.95 cw(c3753.19,3257.38) J3.2@3838.45,3342.64 ; 3765.1,3217.86 ccw(c3647.33,3335.63) J3.2@3812.98,3352.94 ; J4.13@3768.91,3152.95 ccw(c3817.87,3152.95) 3783.25,3118.33 ; J4.13@3768.91,3168.7 cw(c3896.78,3168.7) 3806.36,3259.12 ; 3794.31,3247.06 ccw(c3700.22,3341.16) J3.2@3832.56,3354.99 ; 3800.71,3377.95 cw(c3800.71,3304.9) J3.2@3852.37,3356.56 ; 3806.28,3377.95 ccw(c3806.28,3403.75) J3.2@3824.53,3385.51 ; 3823.51,3276.27 ccw(c3753.1,3346.68) J3.2@3852.14,3357.03 ; 3852.72,3305.47 ccw(c3805.98,3352.21) J3.2@3871.72,3359.08
  Bottom Layer w19.68: Temp1.6@3729.11,1643.7 Temp1.6@3729.11,1744.85
LED_ACT: R26.2 R35.2 U5.26 | length 1378.8
  Top Layer w8: v1@3235.09,2366.14 cw(c3213.37,2366.14) 3228.73,2350.78 cw(c3244.09,2335.41) v1@3244.09,2357.14 ; v1(3244.09,2366.14) 3208.66,2330.71 3153.54,2330.71 3110.95,2373.3 3110.95,2418.44 3133.02,2440.51 3133.02,2614.24 3247.19,2728.42 3247.19,2825.79 3179.42,2893.56 3179.42,3018 v1(3322.83,3161.42) ; v1@3313.83,3161.42 cw(c3292.11,3161.42) 3307.47,3146.05 cw(c3322.83,3130.69) v1@3322.83,3152.42
  Bottom Layer w8: U5.26@3155.51,2328.74 3206.69,2328.74 v1(3244.09,2366.14) ; v1@3235.09,2366.14 cw(c3213.37,2366.14) 3228.73,2350.78 cw(c3244.09,2335.41) v1@3244.09,2357.14
  Bottom Layer w39.37: R26.2@3322.83,3122.05 R35.2@3322.83,3196.85
LED_LINK: R19.2 R25.2 U5.28 | length 1684
  Top Layer w10: v1@3238.44,2292.57 ccw(c3224.78,2278.91) 3224.78,2298.23 ccw(c3224.78,2317.54) v1@3238.44,2303.89 ; v1(3244.09,2298.23) 3159.38,2298.23 3092.11,2365.49 3092.11,2426.25 3114.17,2448.31 3114.17,2622.05 3228.35,2736.22 3228.35,2817.99 3160.57,2885.76 3160.57,3042.46 3311.02,3192.91 3500,3192.91 v1(3531.5,3161.42) ; v1@3523.5,3161.42 ccw(c3504.18,3161.42) 3517.84,3175.07 ccw(c3531.5,3188.73) v1@3531.5,3169.42
  Bottom Layer w8: U5.28@3155.51,2289.37 v1@3246.06,2289.37 ; 3200.98,2289.37 ccw(c3200.98,2341.34) v1@3237.73,2304.59 ; 3220.29,2289.37 ccw(c3220.29,2322.03) v1@3243.39,2298.94
  Bottom Layer w39.37: R19.2@3531.5,3122.05 R25.2@3531.5,3200.79
NetC12_1: C12.1 U3.3 | length 222.6
  Bottom Layer w20: U3.3@3822.83,2425.2 3866.14,2381.89 C12.1@3905.51,2381.89 ; U3.3@3824.41,2403.11 cw(c3824.41,2353.59) 3859.43,2388.61 ; U3.3@3846.89,2425.59 ccw(c3905.91,2425.59) 3864.18,2383.85 ; C12.1@3898.66,2375.04 ccw(c3882.13,2358.51) 3882.13,2381.89 ccw(c3882.13,2405.27) C12.1@3898.66,2388.74
NetC13_1: C13.1 U3.8 | length 160.8
  Bottom Layer w20: C13.1@3734.25,1893.7 3791.34,1893.7 U3.8@3822.83,1925.2 ; C13.1@3745.28,1882.68 cw(c3771.89,1856.06) 3771.89,1893.7 cw(c3771.89,1931.34) C13.1@3745.28,1904.73
NetC24_1: C24.1 U4.3 | length 277.3
  Bottom Layer w20: U4.3@4214.17,2189.37 4287.8,2189.37 4314.96,2216.54 C24.1@4314.96,2259.84 ; U4.3@4230.07,2173.47 cw(c4268.45,2135.1) 4268.45,2189.37 cw(c4268.45,2243.64) U4.3@4230.07,2205.27 ; C24.1@4308.11,2256.93 cw(c4291.58,2240.4) 4314.96,2240.4 cw(c4338.34,2240.4) C24.1@4321.81,2256.93
NetC25_1: C25.1 U4.8 | length 317
  Top Layer w20: C25.1@4136.61,1564.17 ccw(c4110,1590.79) 4147.64,1590.79 ccw(c4185.28,1590.79) C25.1@4158.66,1564.17 ; C25.1@4147.64,1543.31 4147.64,1624.02 U4.8@4212.6,1688.98 ; 4173.78,1650.16 cw(c4214.17,1609.77) U4.8@4214.17,1666.89 ; 4176.63,1653.01 ccw(c4140.27,1689.37) U4.8@4191.69,1689.37
NetC30_2: C30.2 U5.33 | length 266.8
  Bottom Layer w8: U5.33@3155.51,2190.94 3202.75,2190.94 3251.97,2141.72 3251.97,2117.98 C30.2@3299.15,2070.8 ; 3272.22,2097.73 ccw(c3299.21,2124.72) C30.2@3299.21,2086.55 ; 3272.53,2097.43 cw(c3245.96,2070.87) C30.2@3283.53,2070.87
NetC34_2: C34.2 C35.2 C36.2 C37.1 U5.18 U5.23 U5.37 | length 1541.6
  Top Layer w10: C36.2@2854.33,2440.94 2948.82,2440.94 2984.25,2405.51 v1@2984.25,2338.58 ; C36.2@2864.71,2430.56 cw(c2889.78,2405.49) 2889.78,2440.94 cw(c2889.78,2476.4) C36.2@2864.71,2451.33 ; v1@2978.42,2346.66 ccw(c2964.35,2360.73) 2984.25,2360.73 ; 2984.25,2359.89 ccw(c3002.97,2359.89) v1@2989.74,2346.66
  Bottom Layer w8: v1@2977.71,2334.64 cw(c2961.93,2318.85) 2984.25,2318.85 ; v1@2977.89,2346.93 ccw(c2962.52,2362.3) 2984.25,2362.3 ccw(c3005.98,2362.29) v1@2990.62,2346.93 ; 2984.25,2319.69 cw(c3005.39,2319.69) v1@2990.44,2334.64 ; U5.18@2984.25,2401.57 2984.25,2340.55 2984.25,2311.42 2999.21,2296.46 3073.58,2296.46 3089.83,2312.72 3089.83,2334.95 3082.68,2342.11 U5.23@3082.68,2401.57 3082.68,2444.88 3122.05,2484.25 C34.2@3153.54,2484.25 ; 3057.48,2295.28 3057.48,2256.61 3093.07,2221.02 3093.07,2147.09 3102.3,2137.86 3102.3,2078.8 U5.37@3102.36,2078.74 ; U5.37@3102.95,2040.75 3119.09,2024.61 C35.2@3119.09,1976.38 ; U5.37@3104.27,2043.31 ccw(c3113.62,2043.31) 3107.01,2036.69 ; C35.2@3107.02,1983.53 ccw(c3077.87,2012.68) 3119.09,2012.68 ; C35.2@3112.68,1977.88 ccw(c3097.18,1993.37) 3119.09,1993.37 ; 3119.09,2007.93 ccw(c3153.6,2007.93) C35.2@3129.2,1983.53 ; C34.2@3138.08,2484.25 ccw(c3138.08,2500.03) C34.2@3153.86,2500
  Bottom Layer w10: C35.2@3110.24,1972.44 C35.2@3118.11,1972.44 3173.23,1972.44 3228.35,1917.32 C37.1@3283.46,1917.32 ; C35.2@3128.49,1962.06 cw(c3153.56,1936.99) 3153.56,1972.44 cw(c3153.56,2007.89) C35.2@3128.49,1982.82 ; C37.1@3268.9,1902.76 ccw(c3233.75,1867.61) 3233.75,1917.32 ccw(c3233.75,1967.03) C37.1@3268.9,1931.88
  other v1: 2984.08,2341
NetC49_1: C49.1 U1.49 | length 104.3
  Bottom Layer w8: C49.1@1960.63,2401.57 1984.25,2425.2 U1.49@2055.12,2425.2
NetC50_1: C50.1 U1.73 | length 292.5
  Bottom Layer w8: C50.1@2520.48,2591.27 cw(c2455.88,2526.67) U1.73@2547.24,2526.67 ; C50.1@2526.14,2596.93 cw(c2475.19,2545.98) 2547.24,2545.98 ; C50.1@2531.8,2602.58 cw(c2494.51,2565.29) 2547.24,2565.29 ; C50.1@2537.45,2608.24 cw(c2513.82,2584.61) C50.1@2547.24,2584.61 ; U1.73@2547.24,2505.91 C50.1@2547.24,2602.36
NetD2_2: D2.2 R51.2 | length 3405.7
  Bottom Layer w10: R51.2@1890.83,2649.61 ccw(c1855.37,2649.61) 1880.44,2674.68 ccw(c1905.51,2699.74) R51.2@1905.51,2664.29 ; R51.2@1905.51,2649.61 1863.19,2691.93 1863.19,2867.13 1933.23,2937.17 1933.23,3102.71 1807.54,3228.4 1807.54,3349.27 1891.13,3432.86 1991.92,3432.86 2161.42,3602.36 4007.87,3602.36 D2.2@4066.93,3543.31 ; 4019.68,3590.55 cw(c3972.43,3543.31) D2.2@4039.25,3543.31 ; 4022.53,3587.7 ccw(c4065.75,3630.92) D2.2@4065.75,3569.8 ; 4036.75,3573.48 cw(c4006.58,3543.31) D2.2@4049.25,3543.31 ; 4039.6,3570.63 ccw(c4065.75,3596.78) D2.2@4065.75,3559.8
